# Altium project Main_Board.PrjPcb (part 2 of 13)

## Sheet LED_US_1.SchDoc: LED_US_1
size A3
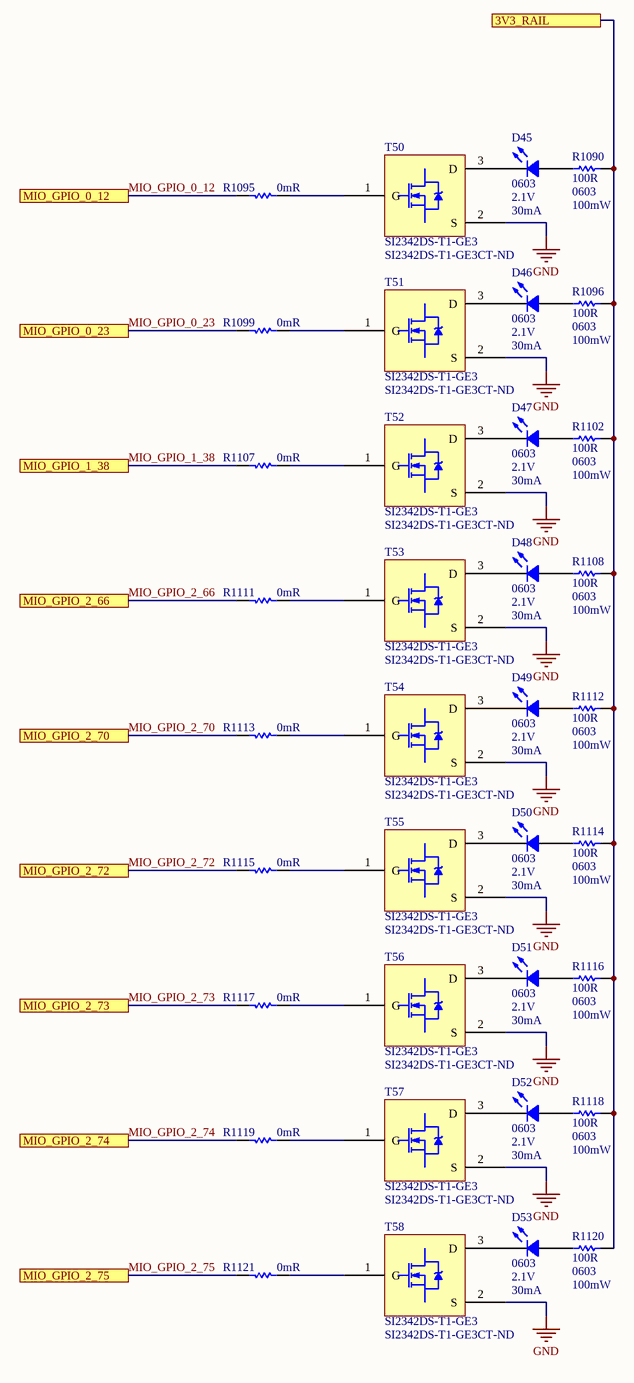
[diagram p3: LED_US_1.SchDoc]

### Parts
D45  Case Code (Imperial): 0603  Forward Voltage: 2.1V  Forward Current: 30mA  [LED 0603/1608 GREEN]  (hidden comment: LTST-C190GKT)
D46  Case Code (Imperial): 0603  Forward Voltage: 2.1V  Forward Current: 30mA  [LED 0603/1608 GREEN]  (hidden comment: LTST-C190GKT)
D47  Case Code (Imperial): 0603  Forward Voltage: 2.1V  Forward Current: 30mA  [LED 0603/1608 GREEN]  (hidden comment: LTST-C190GKT)
D48  Case Code (Imperial): 0603  Forward Voltage: 2.1V  Forward Current: 30mA  [LED 0603/1608 GREEN]  (hidden comment: LTST-C190GKT)
D49  Case Code (Imperial): 0603  Forward Voltage: 2.1V  Forward Current: 30mA  [LED 0603/1608 GREEN]  (hidden comment: LTST-C190GKT)
D50  Case Code (Imperial): 0603  Forward Voltage: 2.1V  Forward Current: 30mA  [LED 0603/1608 GREEN]  (hidden comment: LTST-C190GKT)
D51  Case Code (Imperial): 0603  Forward Voltage: 2.1V  Forward Current: 30mA  [LED 0603/1608 GREEN]  (hidden comment: LTST-C190GKT)
D52  Case Code (Imperial): 0603  Forward Voltage: 2.1V  Forward Current: 30mA  [LED 0603/1608 GREEN]  (hidden comment: LTST-C190GKT)
D53  Case Code (Imperial): 0603  Forward Voltage: 2.1V  Forward Current: 30mA  [LED 0603/1608 GREEN]  (hidden comment: LTST-C190GKT)
R1090  100R  Case/Package: 0603  Power Rating: 100mW  [RES 0603/1608 RF]
R1095  0mR  [RES 0402/1005 RF KK]
R1096  100R  Case/Package: 0603  Power Rating: 100mW  [RES 0603/1608 RF]
R1099  0mR  [RES 0402/1005 RF KK]
R1102  100R  Case/Package: 0603  Power Rating: 100mW  [RES 0603/1608 RF]
R1107  0mR  [RES 0402/1005 RF KK]
R1108  100R  Case/Package: 0603  Power Rating: 100mW  [RES 0603/1608 RF]
R1111  0mR  [RES 0402/1005 RF KK]
R1112  100R  Case/Package: 0603  Power Rating: 100mW  [RES 0603/1608 RF]
R1113  0mR  [RES 0402/1005 RF KK]
R1114  100R  Case/Package: 0603  Power Rating: 100mW  [RES 0603/1608 RF]
R1115  0mR  [RES 0402/1005 RF KK]
R1116  100R  Case/Package: 0603  Power Rating: 100mW  [RES 0603/1608 RF]
R1117  0mR  [RES 0402/1005 RF KK]
R1118  100R  Case/Package: 0603  Power Rating: 100mW  [RES 0603/1608 RF]
R1119  0mR  [RES 0402/1005 RF KK]
R1120  100R  Case/Package: 0603  Power Rating: 100mW  [RES 0603/1608 RF]
R1121  0mR  [RES 0402/1005 RF KK]
T50  SI2342DS-T1-GE3  Supplier Part Number 1: SI2342DS-T1-GE3CT-ND  [SI2342DS-T1-GE3]
T51  SI2342DS-T1-GE3  Supplier Part Number 1: SI2342DS-T1-GE3CT-ND  [SI2342DS-T1-GE3]
T52  SI2342DS-T1-GE3  Supplier Part Number 1: SI2342DS-T1-GE3CT-ND  [SI2342DS-T1-GE3]
T53  SI2342DS-T1-GE3  Supplier Part Number 1: SI2342DS-T1-GE3CT-ND  [SI2342DS-T1-GE3]
T54  SI2342DS-T1-GE3  Supplier Part Number 1: SI2342DS-T1-GE3CT-ND  [SI2342DS-T1-GE3]
T55  SI2342DS-T1-GE3  Supplier Part Number 1: SI2342DS-T1-GE3CT-ND  [SI2342DS-T1-GE3]
T56  SI2342DS-T1-GE3  Supplier Part Number 1: SI2342DS-T1-GE3CT-ND  [SI2342DS-T1-GE3]
T57  SI2342DS-T1-GE3  Supplier Part Number 1: SI2342DS-T1-GE3CT-ND  [SI2342DS-T1-GE3]
T58  SI2342DS-T1-GE3  Supplier Part Number 1: SI2342DS-T1-GE3CT-ND  [SI2342DS-T1-GE3]

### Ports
3V3_RAIL, MIO_GPIO_0_12, MIO_GPIO_0_23, MIO_GPIO_1_38, MIO_GPIO_2_66, MIO_GPIO_2_70, MIO_GPIO_2_72, MIO_GPIO_2_73, MIO_GPIO_2_74, MIO_GPIO_2_75

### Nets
GND: T50.2(S) T51.2(S) T52.2(S) T53.2(S) T54.2(S) T55.2(S) T56.2(S) T57.2(S) T58.2(S)  [project net B503_Ground]
3V3_RAIL: R1090.2 R1096.2 R1102.2 R1108.2 R1112.2 R1114.2 R1116.2 R1118.2 R1120.2 ; port 3V3_RAIL
MIO_GPIO_0_12: R1095.2 ; port MIO_GPIO_0_12
MIO_GPIO_0_23: R1099.2 ; port MIO_GPIO_0_23
MIO_GPIO_1_38: R1107.2 ; port MIO_GPIO_1_38
MIO_GPIO_2_66: R1111.2 ; port MIO_GPIO_2_66
MIO_GPIO_2_70: R1113.2 ; port MIO_GPIO_2_70
MIO_GPIO_2_72: R1115.2 ; port MIO_GPIO_2_72  [project net EXPANDER_RESET]
MIO_GPIO_2_73: R1117.2 ; port MIO_GPIO_2_73
MIO_GPIO_2_74: R1119.2 ; port MIO_GPIO_2_74
MIO_GPIO_2_75: R1121.2 ; port MIO_GPIO_2_75
NetD45_1: D45.1 R1090.1
NetD45_2: D45.2 T50.3(D)
NetD46_1: D46.1 R1096.1
NetD46_2: D46.2 T51.3(D)
NetD47_1: D47.1 R1102.1
NetD47_2: D47.2 T52.3(D)
NetD48_1: D48.1 R1108.1
NetD48_2: D48.2 T53.3(D)
NetD49_1: D49.1 R1112.1
NetD49_2: D49.2 T54.3(D)
NetD50_1: D50.1 R1114.1
NetD50_2: D50.2 T55.3(D)
NetD51_1: D51.1 R1116.1
NetD51_2: D51.2 T56.3(D)
NetD52_1: D52.1 R1118.1
NetD52_2: D52.2 T57.3(D)
NetD53_1: D53.1 R1120.1
NetD53_2: D53.2 T58.3(D)
NetR1095_1: R1095.1 T50.1(G)
NetR1099_1: R1099.1 T51.1(G)
NetR1107_1: R1107.1 T52.1(G)
NetR1111_1: R1111.1 T53.1(G)
NetR1113_1: R1113.1 T54.1(G)
NetR1115_1: R1115.1 T55.1(G)
NetR1117_1: R1117.1 T56.1(G)
NetR1119_1: R1119.1 T57.1(G)
NetR1121_1: R1121.1 T58.1(G)

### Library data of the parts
D45-D53 = LTST-C190GKT: LED,  LTST-C190GKT; Manufacturer 1: Vishay Lite-On; Color: Green; Lens Color: Colorless; Luminous Intensity: 6mcd; Viewing Angle: 130°; Lens Style: Clear,Diffused,Colorless,Rectangular; Power Rating: 100mW; Dominant Wavelength: 569nm; Test Current: 10mA; Lens Transparency: Clear; Number of Elements: 1; Wavelength: 565nm; Voltage: 2V; Reverse Voltage: 5V
R1090 R1096 R1102 R1108 R1112 R1114 R1116 R1118 R1120 = Resistor: KOA SPEAR ELECTRONICS - RK73H1JTTD1000F - RES, 100R, 1%, 0.1W, 0603, THICK FILM; Manufacturer: KOA Speer; Voltage Rating: 50V; Temperature Coefficient: 100ppm/°C
R1095 R1099 R1107 R1111 R1113 R1115 R1117 R1119 R1121 = Resistor: Manufacturer 1: Yageo; Manufacturer Part Number 1: RC0402JR-070RL; Power Rating: 62.5mW; Tolerance: 5%; Voltage Rating: 50V; Max Power Dissipation: 63mW; Temperature Coefficient: 200ppm/°C
T50-T58 = SI2342DS-T1-GE3: Trans MOSFET N-CH 8V 6A 3-Pin SOT-23 T/R; Manufacturer: Vishay; Rds On Max: 17mR; Input Capacitance: 1.07nF; Rise Time: 14ns; Max Power Dissipation: 2.5W; Number of Elements: 1; Power Dissipation: 1.3W; Turn-On Delay Time: 6ns; Turn-Off Delay Time: 65ns; Fall Time: 25ns; Threshold Voltage: 800mV; Gate to Source Voltage (Vgs): 5V

## Sheet WR_Clock.SchDoc: WR_Generator
size A3; Organization: Altium Limited; Address1: L3, 12a Rodborough Rd; Address2: Frenchs Forest; Address3: NSW; Address4: Australia 2086
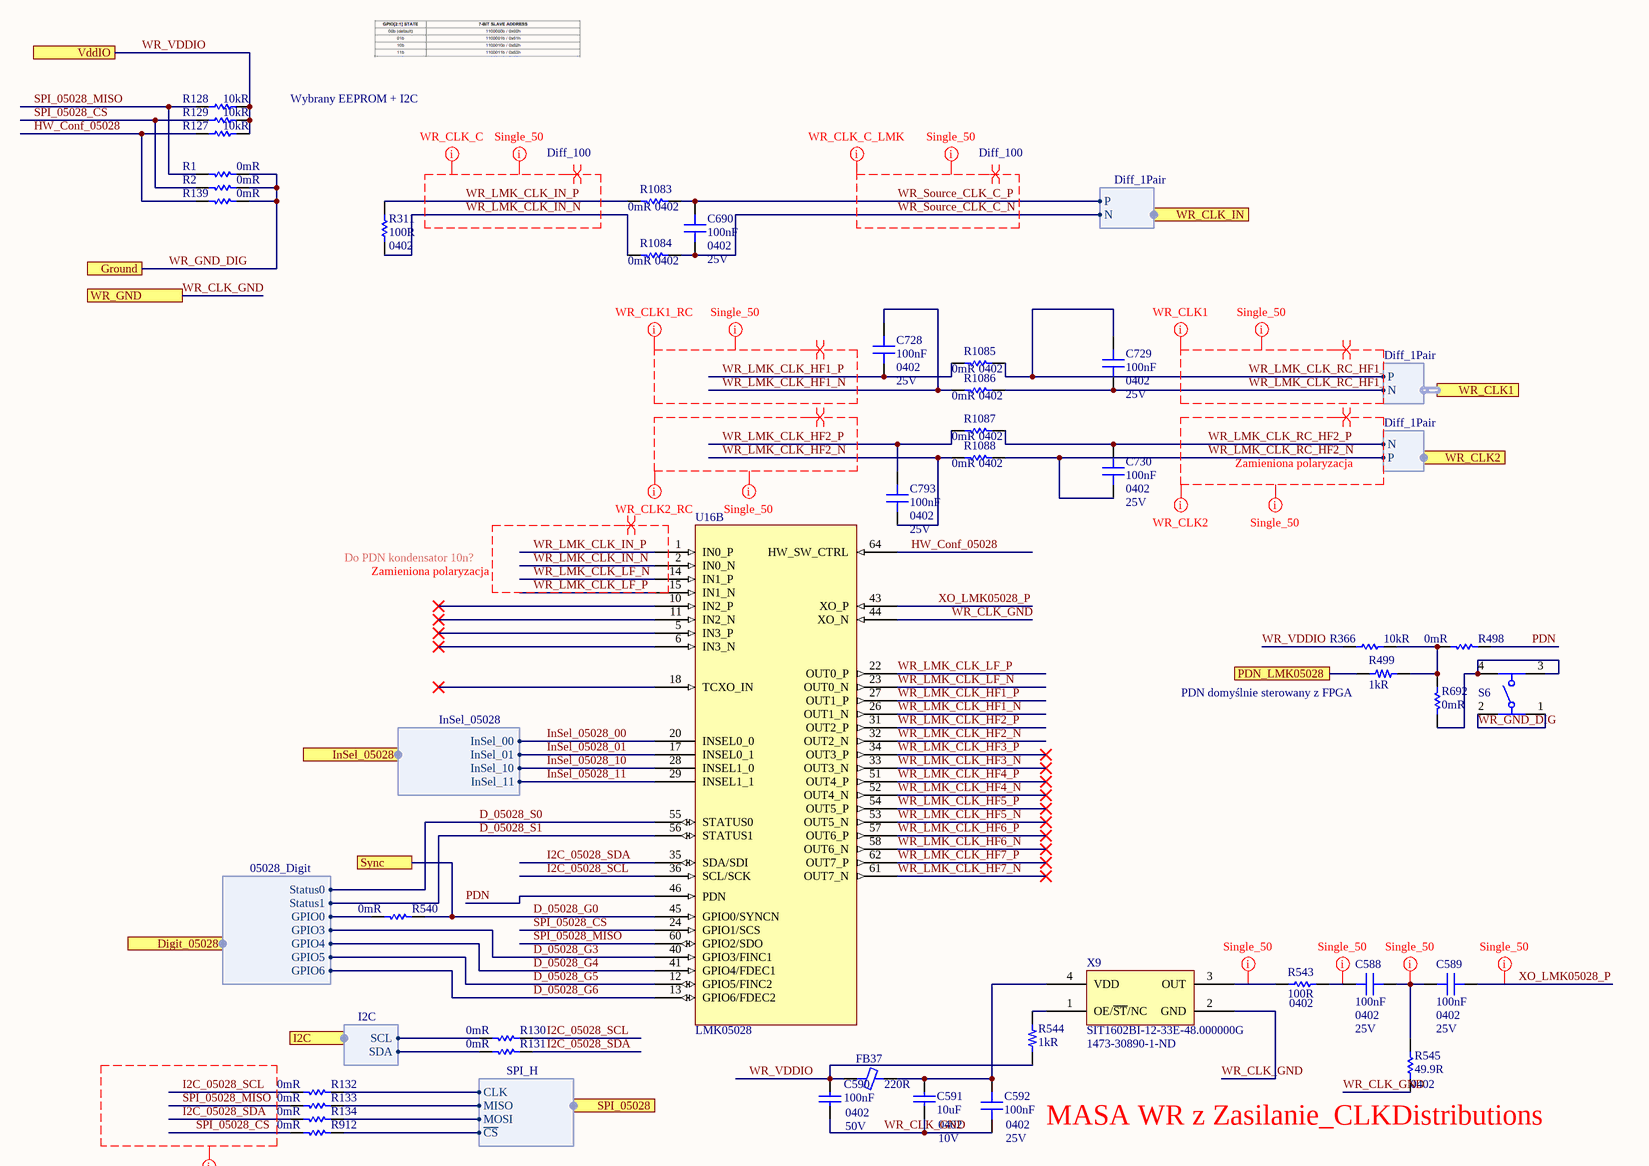
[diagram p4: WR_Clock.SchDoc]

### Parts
C588  100nF  Case/Package: 0402  Voltage Rating: 25V  [CAP 0402/1005 KK]
C589  100nF  Case/Package: 0402  Voltage Rating: 25V  [CAP 0402/1005 KK]
C590  100nF  Case Code (Imperial): 0402  Voltage: 50V  [CAP 0402/1005 KK]
C591  10uF  Case/Package: 0402  Voltage Rating: 10V  [CAP 0402/1005 KK]
C592  100nF  Case/Package: 0402  Voltage Rating: 25V  [CAP 0402/1005 KK]
C690  100nF  Case/Package: 0402  Voltage Rating: 25V  [CAP 0402/1005 KK]
C728  100nF  Case/Package: 0402  Voltage Rating: 25V  [CAP 0402/1005 KK]
C729  100nF  Case/Package: 0402  Voltage Rating: 25V  [CAP 0402/1005 KK]
C730  100nF  Case/Package: 0402  Voltage Rating: 25V  [CAP 0402/1005 KK]
C793  100nF  Case/Package: 0402  Voltage Rating: 25V  [CAP 0402/1005 KK]
FB37  220R  [FER 0603/1608]
R1  0mR  [RES 0402/1005 RF KK]
R2  0mR  [RES 0402/1005 RF KK]
R127  10kR  [RES 0402/1005 RF KK]
R128  10kR  [RES 0402/1005 RF KK]
R129  10kR  [RES 0402/1005 RF KK]
R130  0mR  [RES 0402/1005 RF KK]
R131  0mR  [RES 0402/1005 RF KK]
R132  0mR  [RES 0402/1005 RF KK]
R133  0mR  [RES 0402/1005 RF KK]
R134  0mR  [RES 0402/1005 RF KK]
R139  0mR  [RES 0402/1005 RF KK]
R311  100R  Case/Package: 0402  [RES 0402/1005 RF KK]
R366  10kR  [RES 0402/1005 RF KK]
R498  0mR  [RES 0402/1005 RF KK]
R499  1kR  [RES 0402/1005 RF KK]
R540  0mR  [RES 0402/1005 RF KK]
R543  100R  Case/Package: 0402  [RES 0402/1005 RF KK]
R544  1kR  [RES 0402/1005 RF KK]
R545  49.9R  Case/Package: 0402  [RES 0402/1005 RF KK]
R692  0mR  [RES 0402/1005 RF KK]
R912  0mR  [RES 0402/1005 RF KK]
R1083  0mR  Case/Package: 0402  [RES 0402/1005 RF KK]
R1084  0mR  Case/Package: 0402  [RES 0402/1005 RF KK]
R1085  0mR  Case/Package: 0402  [RES 0402/1005 RF KK]
R1086  0mR  Case/Package: 0402  [RES 0402/1005 RF KK]
R1087  0mR  Case/Package: 0402  [RES 0402/1005 RF KK]
R1088  0mR  Case/Package: 0402  [RES 0402/1005 RF KK]
S6  430181038816  [430181038816]  (value not drawn)
U16  LMK05028  [LMK05028]  (part B of 2)
X9  SIT1602BI-12-33E-48.000000G  Supplier Part Number 1: 1473-30890-1-ND  [SiT1602B]

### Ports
Digit_05028 (harness 05028_Digit), Ground, I2C (harness I2C), InSel_05028 (harness InSel_05028), PDN_LMK05028, SPI_05028 (harness SPI_H), Sync, VddIO, WR_CLK1 (harness Diff_1Pair), WR_CLK2 (harness Diff_1Pair), WR_CLK_IN (harness Diff_1Pair), WR_GND

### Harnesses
SPI_H: CLK, MISO, MOSI, ~{CS}
I2C: SDA, SCL
05028_Digit: GPIO4, GPIO3, Status0, GPIO6, Status1, GPIO5, GPIO0
Diff_1Pair: N, P
InSel_05028: InSel_00, InSel_01, InSel_10, InSel_11

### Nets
WR_GND_DIG: R1.1 R2.1 R139.1 S6.1 S6.2 ; port Ground  [project net B503_Ground]
D_05028_G0: R540.1 U16.45(GPIO0/SYNCN) ; port Sync
D_05028_G3: U16.40(GPIO3/FINC1) ; port Digit_05028.GPIO3
D_05028_G4: U16.41(GPIO4/FDEC1) ; port Digit_05028.GPIO4
D_05028_G5: U16.12(GPIO5/FINC2) ; port Digit_05028.GPIO5
D_05028_G6: U16.13(GPIO6/FDEC2) ; port Digit_05028.GPIO6
D_05028_S0: U16.55(STATUS0) ; port Digit_05028.Status0
D_05028_S1: U16.56(STATUS1) ; port Digit_05028.Status1
GPIOa_11.GPIO7: R499.1 ; port PDN_LMK05028
GPIOb_12.GPIO2: R540.2 ; port Digit_05028.GPIO0
HW_Conf_05028: R127.1 R139.2 U16.64(HW_SW_CTRL)
I2C_05028_SCL: R130.1 R132.2 U16.36(SCL/SCK)
I2C_05028_SDA: R131.1 R134.2 U16.35(SDA/SDI)
InSel_05028_00: U16.20(INSEL0_0) ; port InSel_05028.InSel_00  [project net GPIOb_00.GPIO6]
InSel_05028_01: U16.17(INSEL0_1) ; port InSel_05028.InSel_01  [project net GPIOb_00.GPIO7]
InSel_05028_10: U16.28(INSEL1_0) ; port InSel_05028.InSel_10  [project net GPIOb_00.GPIO5]
InSel_05028_11: U16.29(INSEL1_1) ; port InSel_05028.InSel_11  [project net GPIOb_00.GPIO4]
PDN: R498.1 U16.46(PDN)
SFP_I2C4.SCL: R130.2 ; port I2C.SCL
SFP_I2C4.SDA: R131.2 ; port I2C.SDA
SPI_05028_CS: R2.2 R129.1 R912.2 U16.24(GPIO1/SCS)
SPI_05028_MISO: R1.2 R128.1 R133.2 U16.60(GPIO2/SDO)
WR_CLK_GND: C590.1 C591.1 C592.1 R545.1 U16.44(XO_N) X9.2(GND) ; port WR_GND  [project net Ground]
WR_LMK_CLK_HF1_N: C728.1 R1086.2 U16.26(OUT1_N)
WR_LMK_CLK_HF1_P: C728.2 R1085.2 U16.27(OUT1_P)
WR_LMK_CLK_HF2_N: C793.2 R1088.2 U16.32(OUT2_N)
WR_LMK_CLK_HF2_P: C793.1 R1087.2 U16.31(OUT2_P)
WR_LMK_CLK_HF3_N: U16.33(OUT3_N)
WR_LMK_CLK_HF3_P: U16.34(OUT3_P)
WR_LMK_CLK_HF4_N: U16.52(OUT4_N)
WR_LMK_CLK_HF4_P: U16.51(OUT4_P)
WR_LMK_CLK_HF5_N: U16.53(OUT5_N)
WR_LMK_CLK_HF5_P: U16.54(OUT5_P)
WR_LMK_CLK_HF6_N: U16.58(OUT6_N)
WR_LMK_CLK_HF6_P: U16.57(OUT6_P)
WR_LMK_CLK_HF7_N: U16.61(OUT7_N)
WR_LMK_CLK_HF7_P: U16.62(OUT7_P)
WR_LMK_CLK_IN_N: R311.1 R1084.2 U16.2(IN0_N)
WR_LMK_CLK_IN_P: R311.2 R1083.2 U16.1(IN0_P)
WR_LMK_CLK_LF_N: U16.14(IN1_P) U16.23(OUT0_N)
WR_LMK_CLK_LF_P: U16.15(IN1_N) U16.22(OUT0_P)
WR_LMK_CLK_RC_HF1_N: C729.2 R1086.1 ; port WR_CLK1.N
WR_LMK_CLK_RC_HF1_P: C729.1 R1085.1 ; port WR_CLK1.P
WR_LMK_CLK_RC_HF2_N: C730.2 R1088.1 ; port WR_CLK2.P
WR_LMK_CLK_RC_HF2_P: C730.1 R1087.1 ; port WR_CLK2.N
WR_Source_CLK_C_N: C690.2 R1084.1 ; port WR_CLK_IN.N  [project net LTC6952_1_MATCH_Out8_N]
WR_Source_CLK_C_P: C690.1 R1083.1 ; port WR_CLK_IN.P  [project net LTC6952_1_MATCH_Out8_P]
WR_VDDIO: C590.2 FB37.1 R127.2 R128.2 R129.2 R366.1 R544.2 ; port VddIO  [project net VDD_DIG]
XO_LMK05028_P: C589.1 U16.43(XO_P)
NetC588_1: C588.1 C589.2 R545.2
NetC588_2: C588.2 R543.2
NetC591_2: C591.2 C592.2 FB37.2 X9.4(VDD)
NetR132_1: R132.1 ; port SPI_05028.CLK
NetR133_1: R133.1 ; port SPI_05028.MISO
NetR134_1: R134.1 ; port SPI_05028.MOSI
NetR240_SPI_bridge_Main_1: R912.1 ; port SPI_05028.~{CS}
NetR366_2: R366.2 R498.2 R499.2 R692.1
NetR543_1: R543.1 X9.3(OUT)
NetR544_1: R544.1 X9.1(OE/~{ST}/NC)
NetR692_2: R692.2 S6.3 S6.4

Not connected (* = marked no-connect by the designer): U16 5(IN3_P)* 6(IN3_N)* 10(IN2_P)* 11(IN2_N)* 18(TCXO_IN)*

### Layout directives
net class Single_50: NetC588_1, NetC588_2, NetR543_1, WR_LMK_CLK_HF1_N, WR_LMK_CLK_HF1_P, WR_LMK_CLK_HF2_N, WR_LMK_CLK_HF2_P, WR_LMK_CLK_IN_N, WR_LMK_CLK_IN_P, WR_LMK_CLK_RC_HF1_N, WR_LMK_CLK_RC_HF1_P, WR_LMK_CLK_RC_HF2_N, WR_LMK_CLK_RC_HF2_P, WR_Source_CLK_C_N, WR_Source_CLK_C_P, XO_LMK05028_P
net class WR_CLK1: WR_LMK_CLK_RC_HF1_N, WR_LMK_CLK_RC_HF1_P
net class WR_CLK2: WR_LMK_CLK_RC_HF2_N, WR_LMK_CLK_RC_HF2_P
net class WR_CLK_C_LMK: WR_Source_CLK_C_N, WR_Source_CLK_C_P
differential pair; differential pair class Diff_100: WR_LMK_CLK_HF1_N, WR_LMK_CLK_HF1_P, WR_LMK_CLK_HF2_N, WR_LMK_CLK_HF2_P, WR_LMK_CLK_IN_N, WR_LMK_CLK_IN_P, WR_LMK_CLK_LF_N, WR_LMK_CLK_LF_P, WR_LMK_CLK_RC_HF1_N, WR_LMK_CLK_RC_HF1_P, WR_LMK_CLK_RC_HF2_N, WR_LMK_CLK_RC_HF2_P, WR_Source_CLK_C_N, WR_Source_CLK_C_P
net class WR_CLK_C: WR_LMK_CLK_IN_N, WR_LMK_CLK_IN_P
net class WR_CLK2_RC: WR_LMK_CLK_HF2_N, WR_LMK_CLK_HF2_P
net class WR_CLK1_RC: WR_LMK_CLK_HF1_N, WR_LMK_CLK_HF1_P
net class SPI_05028: I2C_05028_SCL, I2C_05028_SDA, SPI_05028_CS, SPI_05028_MISO

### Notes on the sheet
- Wybrany EEPROM + I2C
- Zamieniona polaryzacja
- Do PDN kondensator 10n?
- (near R499) PDN domyślnie sterowany z FPGA
- (near R545) MASA WR z Zasilanie_CLKDistributions

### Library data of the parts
C588 C589 C592 C690 C728-C730 C793 = Capacitor: Manufacturer: Murata; Manufacturer Part Number: GRM155R71E104KE14J; Tolerance: 10%; Dielectric: X7R
C590 = Capacitor: CAP CER 0.1UF 50V X5R 0402; Manufacturer: Murata; Manufacturer Part Number: GRM155R61H104KE14D; Dielectric Material: Ceramic; Dissipation Factor: 0.025%; Tolerance: 10%
C591 = Capacitor: CAP CER 10UF 10V X5R 0402; Manufacturer: Samsung; Manufacturer Part Number: CL05A106MP8NUB8; Tolerance: 20%
FB37 = Ferrite: FERRITE BEAD 220 OHM 0603 1LN; Manufacturer: Murata; Manufacturer Part Number: BLM18SG221TN1D; Material: Ferrite,Steel; Tolerance: 25%; Max Current Rating: 2.5A; Number of Lines: 1; DC Resistance (DCR): 40mR; Test Frequency: 100MHz
R1 R2 R130-R134 R139 R498 R540 R692 R912 R1083-R1088 = Resistor: as R1095 on sheet LED_US_1
R127-R129 R366 = Resistor: Manufacturer 1: Yageo; Manufacturer Part Number 1: RC0402FR-0710KL; Tolerance: 1%; Temperature Coefficient: 100ppm/°C; Voltage Rating: 50V; Power Rating: 62.5mW
R311 R543 = Resistor: RES SMD 100 OHM 1% 1/16W 0402; Manufacturer: Yageo; Manufacturer Part Number: RC0402FR-07100RL; Power Rating: 62.5mW; Voltage Rating: 50V; Temperature Coefficient: 100ppm/°C
R499 R544 = Resistor: Manufacturer: Panasonic; Manufacturer Part Number: ERJ-2RKF1001X; Tolerance: 1%; Power Rating: 100mW; Temperature Coefficient: 100ppm/°C; Voltage Rating: 50V
R545 = Resistor: RES SMD 49.9 OHM 1% 1/16W 0402; Manufacturer: Yageo; Manufacturer Part Number: RC0402FR-0749R9L; Voltage Rating (DC): 50V; Power Rating: 62.5mW; Temperature Coefficient: 100ppm/°C; Max Power Dissipation: 63mW
S6 = 430181038816: WS-TASV SMT Tact Switch 4.5x4.5mm, height 3.8mm, 160gf; Rated Voltage: 12VDC; Rated Current: 50mA; Washable: No
U16 = LMK05028: Manufacturer Part Number: LMK05028RGCR; Manufacturer: Texas Instruments; Number of Inputs: 4; Number of Outputs: 8
X9 = SIT1602BI-12-33E-48.000000G: OSC MEMS 48.0000MHZ LVCMOS SMD; Manufacturer: SiTime; Frequency: 48MHz; Max Supply Current: 4.5mA; Frequency Stability: 25ppm

## Sheet System_CLK.SchDoc: Dystrybutory zegarów
size A3; Organization: Altium Limited; Address1: L3, 12a Rodborough Rd; Address2: Frenchs Forest; Address3: NSW; Address4: Australia 2086
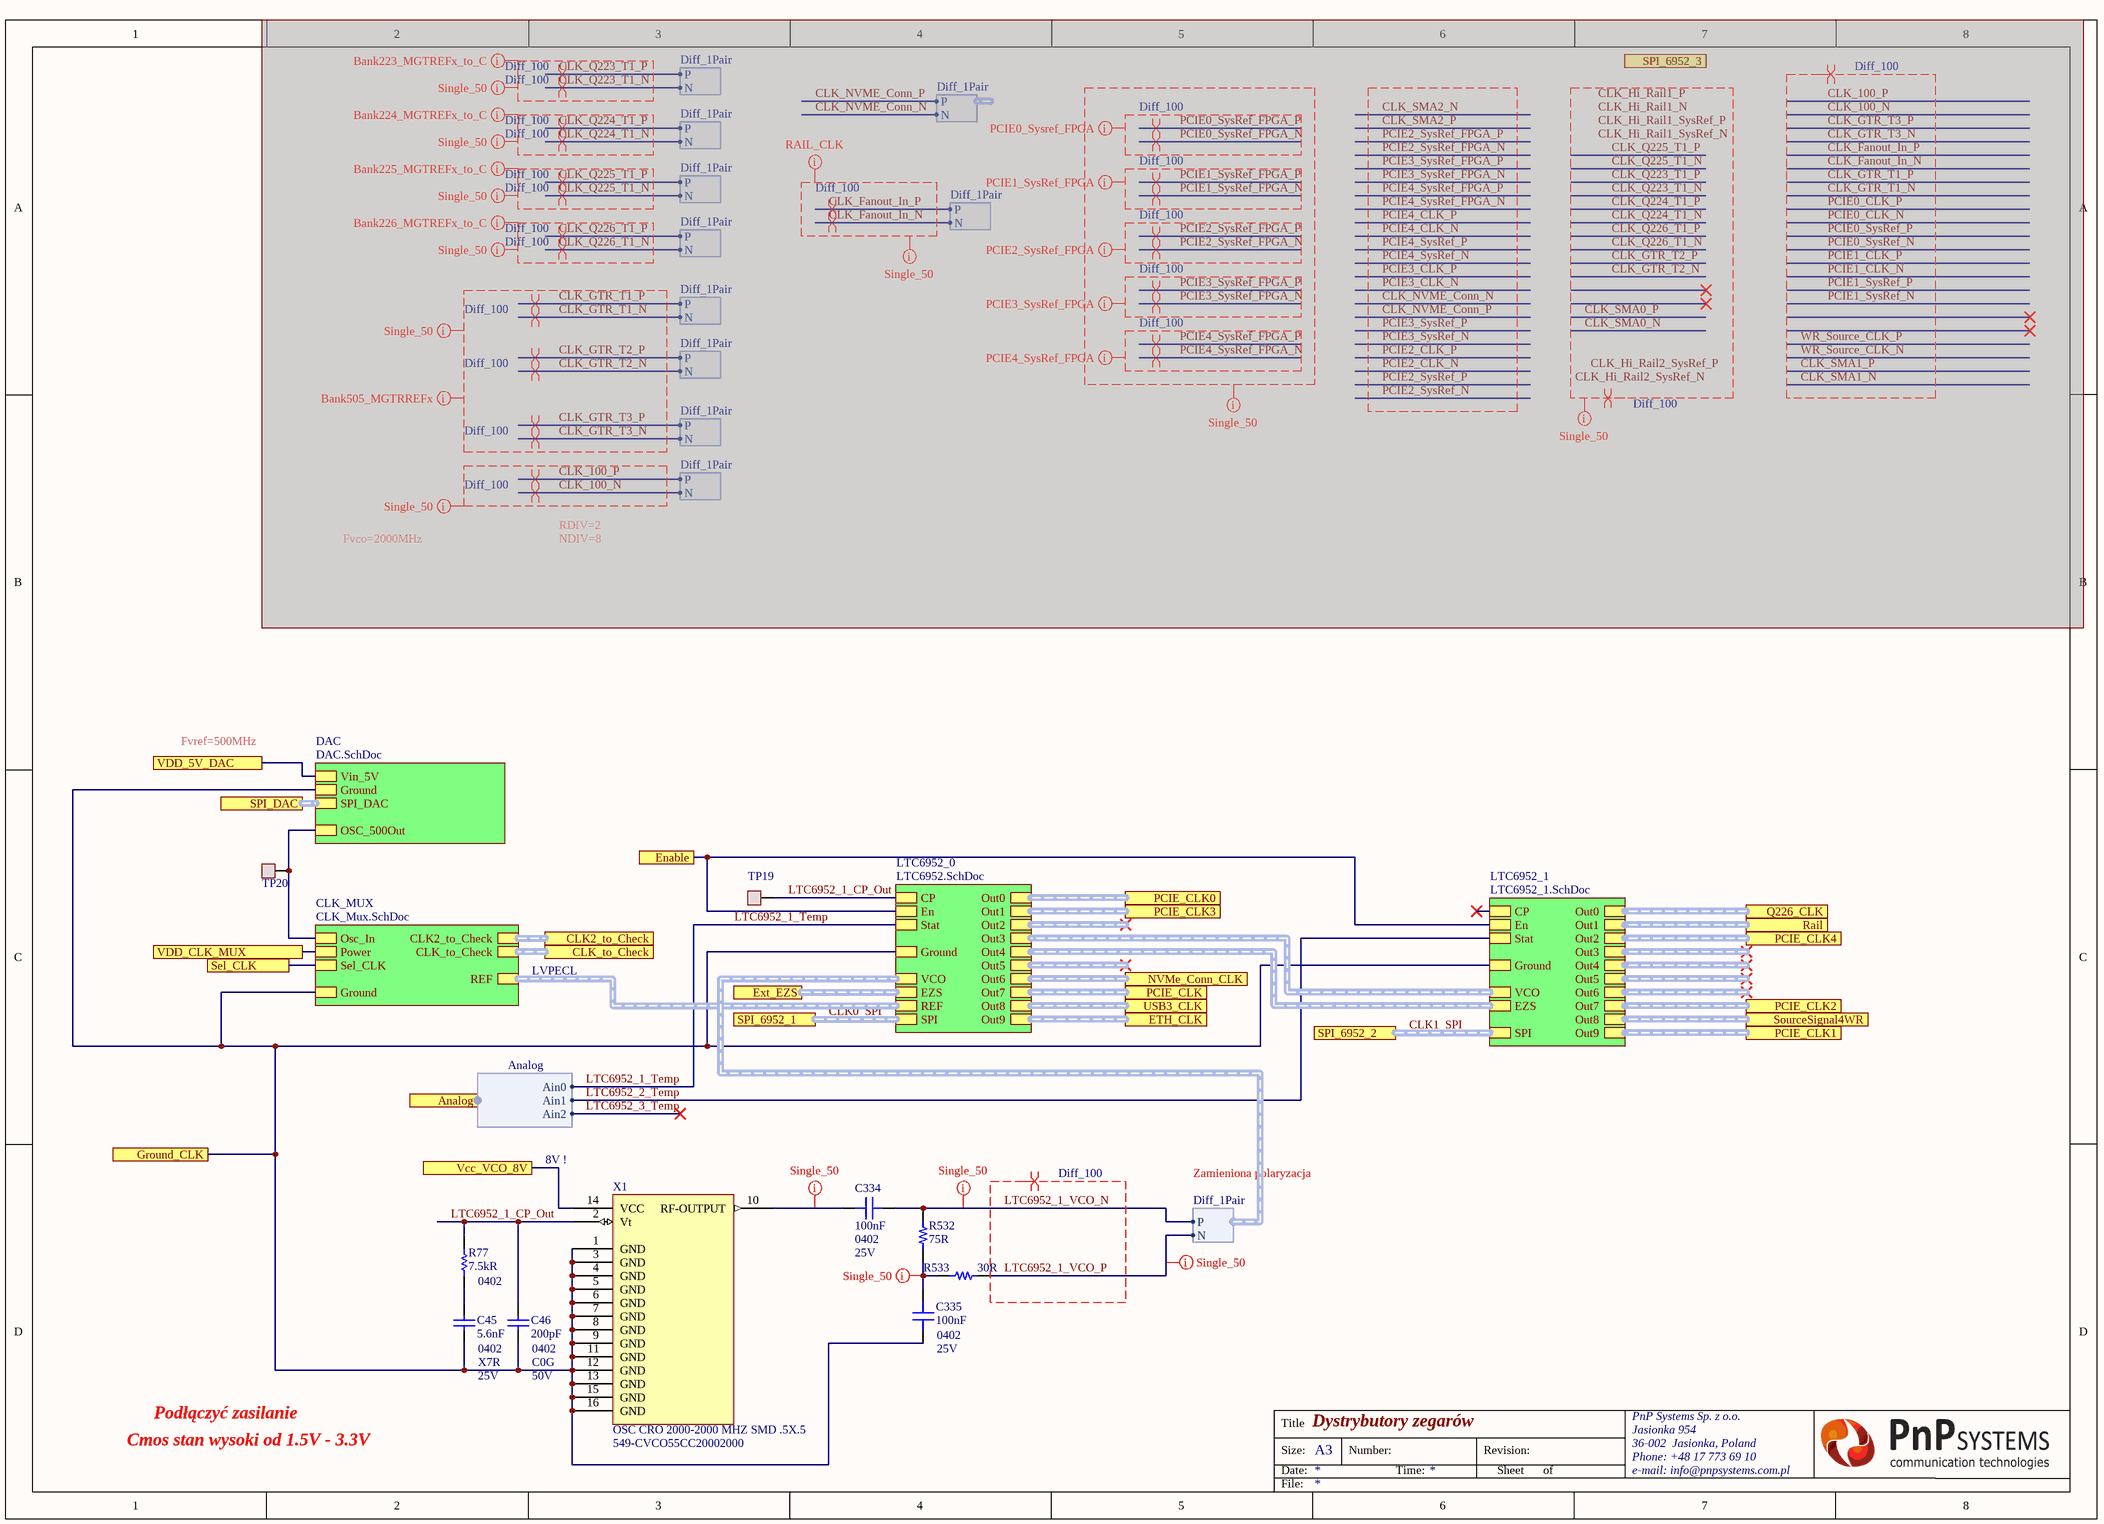
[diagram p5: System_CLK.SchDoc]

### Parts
C45  5.6nF  Case Code (Imperial): 0402  Voltage Rating: 25V  Dielectric: X7R  [CAP 0402/1005 KK]
C46  200pF  Case/Package: 0402  Voltage Rating: 50V  Dielectric: C0G  [CAP 0402/1005 KK]
C334  100nF  Case/Package: 0402  Voltage Rating: 25V  [CAP 0402/1005 KK]
C335  100nF  Case/Package: 0402  Voltage Rating: 25V  [CAP 0402/1005 KK]
R77  7.5kR  Case Code (Imperial): 0402  [RES 0402/1005 RF KK]
R532  75R  [RES 0402/1005 RF KK]
R533  30R  [RES 0402/1005 RF KK]
TP19  TestPoint  [TestPoint]  (value not drawn)
TP20  TestPoint  [TestPoint]  (value not drawn)
X1  OSC CRO 2000-2000 MHZ SMD .5X.5  Supplier Part Number 1: 549-CVCO55CC20002000  [CVCO55CW]

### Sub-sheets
CLK_MUX = CLK_Mux.SchDoc: Sel_CLK, REF (harness Diff_1Pair), Osc_In, Ground, Power, CLK_to_Check (harness Diff_1Pair), CLK2_to_Check (harness Diff_1Pair)
DAC = DAC.SchDoc: Vin_5V, SPI_DAC (harness SPI_H), Ground, OSC_500Out
LTC6952_0 = LTC6952.SchDoc: CP, Ground, Out6 (harness Diff_1Pair), VCO (harness Diff_1Pair), SPI (harness SPI_H), Stat, Out1 (harness Diff_1Pair), En, Out5 (harness Diff_1Pair), Out0 (harness Diff_1Pair), EZS (harness Diff_1Pair), Out2 (harness Diff_1Pair), Out7 (harness Diff_1Pair), REF (harness Diff_1Pair), Out8 (harness Diff_1Pair), Out3 (harness Diff_1Pair), Out4 (harness Diff_1Pair), Out9 (harness Diff_1Pair)
LTC6952_1 = LTC6952_1.SchDoc: EZS (harness Diff_1Pair), SPI (harness SPI_H), En, Out5 (harness Diff_1Pair), Ground, CP, Out4 (harness Diff_1Pair), Out6 (harness Diff_1Pair), VCO (harness Diff_1Pair), Out9 (harness Diff_1Pair), Stat, Out7 (harness Diff_1Pair), Out3 (harness Diff_1Pair), Out0 (harness Diff_1Pair), Out8 (harness Diff_1Pair), Out2 (harness Diff_1Pair), Out1 (harness Diff_1Pair)

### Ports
Analog (harness Analog), CLK2_to_Check (harness Diff_1Pair), CLK_to_Check (harness Diff_1Pair), Enable, ETH_CLK (harness Diff_1Pair), Ext_EZS (harness Diff_1Pair), Ground_CLK, NVMe_Conn_CLK (harness Diff_1Pair), PCIE_CLK0 (harness Diff_1Pair), PCIE_CLK1 (harness Diff_1Pair), PCIE_CLK2 (harness Diff_1Pair), PCIE_CLK3 (harness Diff_1Pair), PCIE_CLK4 (harness Diff_1Pair), PCIE_CLK (harness Diff_1Pair), Q226_CLK (harness Diff_1Pair), Rail (harness Diff_1Pair), Sel_CLK, SourceSignal4WR (harness Diff_1Pair), SPI_6952_1 (harness SPI_H), SPI_6952_2 (harness SPI_H), SPI_6952_3 (harness SPI_H), SPI_DAC (harness SPI_H), USB3_CLK (harness Diff_1Pair), Vcc_VCO_8V, VDD_5V_DAC, VDD_CLK_MUX

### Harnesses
Diff_1Pair: P, N
Analog: Ain0, Ain1, Ain2

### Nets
3V3_RAIL: port VDD_CLK_MUX, sheet CLK_MUX/Power
5V_LN: port VDD_5V_DAC, sheet DAC/Vin_5V
AGND: C45.1 C46.1 C335.1 X1.1(GND) X1.3(GND) X1.4(GND) X1.5(GND) X1.6(GND) X1.7(GND) X1.8(GND) X1.9(GND) X1.11(GND) X1.12(GND) X1.13(GND) X1.15(GND) X1.16(GND) ; port Ground_CLK, sheet DAC/Ground, sheet CLK_MUX/Ground, sheet LTC6952_1/Ground, sheet LTC6952_0/Ground
Enable_CLK: port Enable, sheet LTC6952_1/En, sheet LTC6952_0/En
LTC6952_1_CP_Out: C46.2 R77.2 TP19.1 X1.2(Vt) ; sheet LTC6952_0/CP
LTC6952_1_Temp: sheet LTC6952_0/Stat, port Analog.Ain0
LTC6952_1_VCO_N: C334.1 R532.2 ; sheet LTC6952_0/VCO.P
LTC6952_1_VCO_P: R533.2 ; sheet LTC6952_0/VCO.N
LTC6952_2_Temp: sheet LTC6952_1/Stat, port Analog.Ain1
OSC_500Out: TP20.1 ; sheet DAC/OSC_500Out, sheet CLK_MUX/Osc_In
SetClk_Si53323_2: port Sel_CLK, sheet CLK_MUX/Sel_CLK
NetC45_2: C45.2 R77.1
NetC334_2: C334.2 X1.10(RF-OUTPUT)
NetC335_2: C335.2 R532.1 R533.1
NetC713_2: X1.14(VCC) ; port Vcc_VCO_8V

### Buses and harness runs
harness CLK0_SPI = port SPI_6952_1 = sheet LTC6952_0/SPI
harness CLK1_SPI = port SPI_6952_2 = sheet LTC6952_1/SPI
harness port CLK2_to_Check = sheet CLK_MUX/CLK2_to_Check
harness port CLK_to_Check = sheet CLK_MUX/CLK_to_Check
harness port ETH_CLK = sheet LTC6952_0/Out9
harness port Ext_EZS = sheet LTC6952_0/EZS
harness port NVMe_Conn_CLK = sheet LTC6952_0/Out6
harness port PCIE_CLK0 = sheet LTC6952_0/Out0
harness port PCIE_CLK1 = sheet LTC6952_1/Out9
harness port PCIE_CLK2 = sheet LTC6952_1/Out7
harness port PCIE_CLK3 = sheet LTC6952_0/Out1
harness port PCIE_CLK4 = sheet LTC6952_1/Out2
harness port PCIE_CLK = sheet LTC6952_0/Out7
harness port Q226_CLK = sheet LTC6952_1/Out0
harness port Rail = sheet LTC6952_1/Out1
harness port SourceSignal4WR = sheet LTC6952_1/Out8
harness port SPI_DAC = sheet DAC/SPI_DAC
harness port USB3_CLK = sheet LTC6952_0/Out8
harness sheet CLK_MUX/REF = sheet LTC6952_0/REF
harness sheet LTC6952_0/Out3 = sheet LTC6952_1/VCO
harness sheet LTC6952_0/Out4 = sheet LTC6952_1/EZS

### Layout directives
net class Bank223_MGTREFx_to_C: CLK_Q223_T1_N, CLK_Q223_T1_P
net class Bank224_MGTREFx_to_C: CLK_Q224_T1_N, CLK_Q224_T1_P
net class Bank225_MGTREFx_to_C: CLK_Q225_T1_N, CLK_Q225_T1_P
net class Bank226_MGTREFx_to_C: CLK_Q226_T1_N, CLK_Q226_T1_P
differential pair; differential pair class Diff_100: CLK_100_N, CLK_100_P, CLK_Fanout_In_N, CLK_Fanout_In_P, CLK_GTR_T1_N, CLK_GTR_T1_P, CLK_GTR_T2_N, CLK_GTR_T2_P, CLK_GTR_T3_N, CLK_GTR_T3_P, CLK_Hi_Rail1_N, CLK_Hi_Rail1_P, CLK_Hi_Rail1_SysRef_N, CLK_Hi_Rail1_SysRef_P, CLK_Hi_Rail2_SysRef_N, CLK_Hi_Rail2_SysRef_P, CLK_Q223_T1_N, CLK_Q223_T1_P, CLK_Q224_T1_N, CLK_Q224_T1_P, CLK_Q225_T1_N, CLK_Q225_T1_P, CLK_Q226_T1_N, CLK_Q226_T1_P, CLK_SMA0_N, CLK_SMA0_P, CLK_SMA1_N, CLK_SMA1_P, LTC6952_1_VCO_N, LTC6952_1_VCO_P, PCIE0_CLK_N, PCIE0_CLK_P, PCIE0_SysRef_FPGA_N, PCIE0_SysRef_FPGA_P, PCIE0_SysRef_N, PCIE0_SysRef_P, PCIE1_CLK_N, PCIE1_CLK_P, PCIE1_SysRef_FPGA_N, PCIE1_SysRef_FPGA_P, PCIE1_SysRef_N, PCIE1_SysRef_P, PCIE2_SysRef_FPGA_N, PCIE2_SysRef_FPGA_P, PCIE3_SysRef_FPGA_N, PCIE3_SysRef_FPGA_P, PCIE4_SysRef_FPGA_N, PCIE4_SysRef_FPGA_P, WR_Source_CLK_N, WR_Source_CLK_P
net class Single_50: CLK_100_N, CLK_100_P, CLK_Fanout_In_N, CLK_Fanout_In_P, CLK_GTR_T1_N, CLK_GTR_T1_P, CLK_GTR_T2_N, CLK_GTR_T2_P, CLK_GTR_T3_N, CLK_GTR_T3_P, CLK_Hi_Rail1_N, CLK_Hi_Rail1_P, CLK_Hi_Rail1_SysRef_N, CLK_Hi_Rail1_SysRef_P, CLK_Hi_Rail2_SysRef_N, CLK_Hi_Rail2_SysRef_P, CLK_Q223_T1_N, CLK_Q223_T1_P, CLK_Q224_T1_N, CLK_Q224_T1_P, CLK_Q225_T1_N, CLK_Q225_T1_P, CLK_Q226_T1_N, CLK_Q226_T1_P, CLK_SMA0_N, CLK_SMA0_P, LTC6952_1_VCO_N, LTC6952_1_VCO_P, NetC334_2, NetC335_2, PCIE0_SysRef_FPGA_N, PCIE0_SysRef_FPGA_P, PCIE1_SysRef_FPGA_N, PCIE1_SysRef_FPGA_P, PCIE2_SysRef_FPGA_N, PCIE2_SysRef_FPGA_P, PCIE3_SysRef_FPGA_N, PCIE3_SysRef_FPGA_P, PCIE4_SysRef_FPGA_N, PCIE4_SysRef_FPGA_P
net class Bank505_MGTRREFx_: CLK_GTR_T1_N, CLK_GTR_T1_P, CLK_GTR_T2_N, CLK_GTR_T2_P, CLK_GTR_T3_N, CLK_GTR_T3_P
net class RAIL_CLK: CLK_Fanout_In_N, CLK_Fanout_In_P
net class PCIE0_Sysref_FPGA: PCIE0_SysRef_FPGA_N, PCIE0_SysRef_FPGA_P, PCIE1_SysRef_FPGA_N, PCIE1_SysRef_FPGA_P, PCIE2_SysRef_FPGA_N, PCIE2_SysRef_FPGA_P, PCIE3_SysRef_FPGA_N, PCIE3_SysRef_FPGA_P, PCIE4_SysRef_FPGA_N, PCIE4_SysRef_FPGA_P
net class PCIE1_SysRef_FPGA: PCIE0_SysRef_FPGA_N, PCIE0_SysRef_FPGA_P, PCIE1_SysRef_FPGA_N, PCIE1_SysRef_FPGA_P, PCIE2_SysRef_FPGA_N, PCIE2_SysRef_FPGA_P, PCIE3_SysRef_FPGA_N, PCIE3_SysRef_FPGA_P, PCIE4_SysRef_FPGA_N, PCIE4_SysRef_FPGA_P
net class PCIE2_SysRef_FPGA: PCIE0_SysRef_FPGA_N, PCIE0_SysRef_FPGA_P, PCIE1_SysRef_FPGA_N, PCIE1_SysRef_FPGA_P, PCIE2_SysRef_FPGA_N, PCIE2_SysRef_FPGA_P, PCIE3_SysRef_FPGA_N, PCIE3_SysRef_FPGA_P, PCIE4_SysRef_FPGA_N, PCIE4_SysRef_FPGA_P
net class PCIE3_SysRef_FPGA: PCIE0_SysRef_FPGA_N, PCIE0_SysRef_FPGA_P, PCIE1_SysRef_FPGA_N, PCIE1_SysRef_FPGA_P, PCIE2_SysRef_FPGA_N, PCIE2_SysRef_FPGA_P, PCIE3_SysRef_FPGA_N, PCIE3_SysRef_FPGA_P, PCIE4_SysRef_FPGA_N, PCIE4_SysRef_FPGA_P
net class PCIE4_SysRef_FPGA: PCIE0_SysRef_FPGA_N, PCIE0_SysRef_FPGA_P, PCIE1_SysRef_FPGA_N, PCIE1_SysRef_FPGA_P, PCIE2_SysRef_FPGA_N, PCIE2_SysRef_FPGA_P, PCIE3_SysRef_FPGA_N, PCIE3_SysRef_FPGA_P, PCIE4_SysRef_FPGA_N, PCIE4_SysRef_FPGA_P

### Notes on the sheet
- RDIV=2
- Fvco=2000MHz
- NDIV=8
- Fvref=500MHz
- LVPECL
- 8V !
- Zamieniona polaryzacja
- Cmos stan wysoki od 1.5V - 3.3V
- Podłączyć zasilanie

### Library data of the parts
C45 = Capacitor: Cap Ceramic 0.0056uF 25V X7R 10% SMD 0402 125C Paper T/R; Manufacturer: Yageo; Manufacturer Part Number: CC0402KRX7R8BB562
C46 = Capacitor: Multilayer Ceramic Capacitors MLCC - SMD/SMT 200pF 50V NPO 5%; Manufacturer: Yageo; Manufacturer Part Number: CC0402JRNPO9BN201
C334 C335 = Capacitor: as C588 on sheet WR_Clock
R77 = Resistor: RES SMD 7.5K OHM 0.5% 1/16W 0402; Manufacturer: Susumu; Manufacturer Part Number: RR0510P-752-D; Power Rating: 62.5mW; Voltage Rating: 25V; Max Power Dissipation: 63mW; Temperature Coefficient: 25ppm/°C; Voltage Rating (DC): 50V
R532 = Resistor: Res Thick Film 0402 75 Ohm 1% 1/10W 100ppm/C Molded SMD SMD Punched Carrier T/R; Manufacturer: Panasonic; Manufacturer Part Number: ERJ-2RKF75R0X; Voltage Rating: 50V; Power Rating: 100mW; Temperature Coefficient: 100ppm/°C
R533 = Resistor: RES SMD 30 OHM 0.5% 1/16W 0402; Manufacturer: Panasonic; Manufacturer Part Number: ERA-2AKD300X; Power Rating: 62.5mW; Temperature Coefficient: 100ppm/°C; Max Power Dissipation: 63mW
TP19 TP20 = TestPoint: Manufacturer: Keystone Electronics; Manufacturer Part Number: 5001; Plating: Silver; Body Material: PBT,Bronze; Number of Ports: 1; Insulation: Insulated; Inside Diameter: 1.27mm; Outside Diameter: 2.54mm; Hole Diameter: 1.6mm
X1 = CVCO55CC-2000-2000: Manufacturer: Crystek; Frequency: 2GHz; Load Capacitance: 22pF; Operating Supply Voltage: 8V

## Sheet DAC.SchDoc: DAC
size A4; Organization: Altium Limited; Address1: L3, 12a Rodborough Rd; Address2: Frenchs Forest; Address3: NSW; Address4: Australia 2086
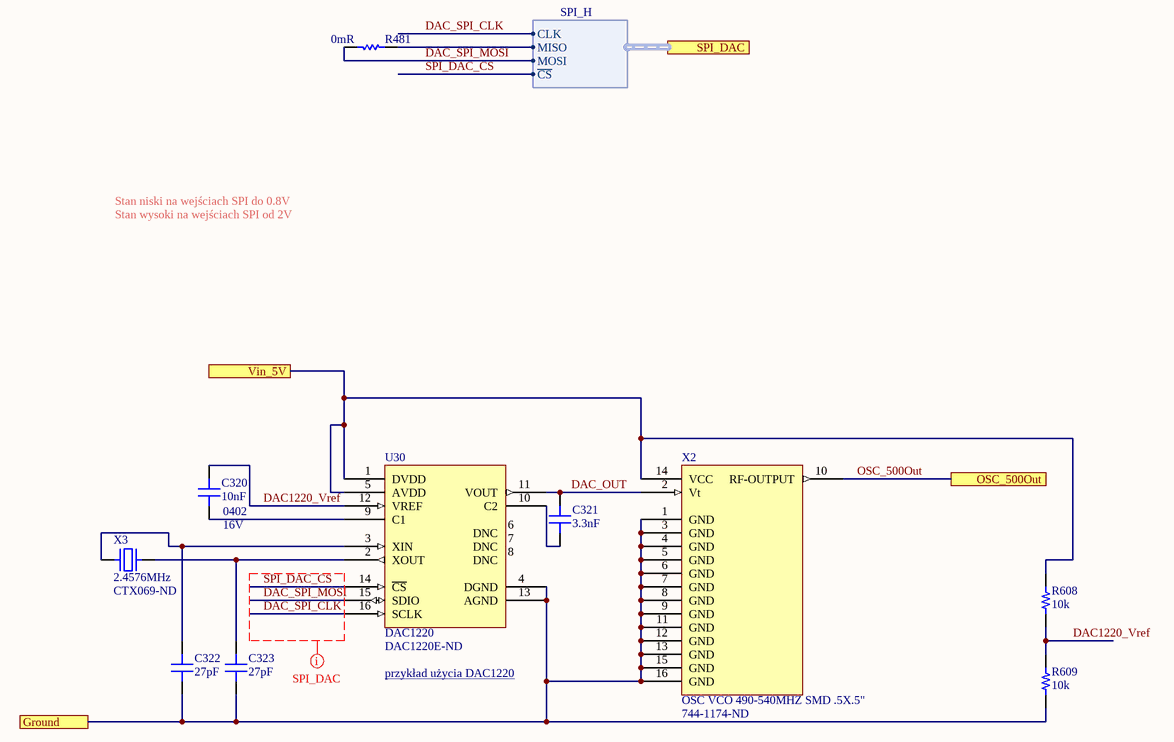
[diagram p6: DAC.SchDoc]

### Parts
C320  10nF  Case/Package: 0402  Voltage Rating (DC): 16V  [CAP 0402/1005 KK]
C321  3.3nF  [CAP 0603/1608 RF]
C322  27pF  [CAP 0402/1005 KK]
C323  27pF  [CAP 0402/1005 KK]
R481  0mR  [RES 0402/1005 RF KK]
R608  10k  [RES 0402/1005 RF KK]
R609  10k  [RES 0402/1005 RF KK]
U30  DAC1220  Supplier Part Number 1: DAC1220E-ND  [DAC1220]
X2  OSC VCO 490-540MHZ SMD .5X.5"  Supplier Part Number 1: 744-1174-ND  [CVCO55CW]
X3  2.4576MHz  Supplier Part Number 1: CTX069-ND  [Crystal]

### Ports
Ground, OSC_500Out, SPI_DAC (harness SPI_H), Vin_5V

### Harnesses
SPI_H: CLK, MISO, MOSI, ~{CS}

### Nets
5V_LN: R608.1 U30.1(DVDD) U30.5(AVDD) X2.14(VCC) ; port Vin_5V
AGND: C322.1 C323.1 R609.2 U30.4(DGND) U30.13(AGND) X2.1(GND) X2.3(GND) X2.4(GND) X2.5(GND) X2.6(GND) X2.7(GND) X2.8(GND) X2.9(GND) X2.11(GND) X2.12(GND) X2.13(GND) X2.15(GND) X2.16(GND) ; port Ground
DAC1220_Vref: C320.1 R608.2 R609.1 U30.12(VREF)
DAC_OUT: C321.2 U30.11(VOUT) X2.2(Vt)
DAC_SPI_CLK: U30.16(SCLK) ; port SPI_DAC.CLK
DAC_SPI_MOSI: R481.1 U30.15(SDIO) ; port SPI_DAC.MOSI
OSC_500Out: X2.10(RF-OUTPUT) ; port OSC_500Out
SPI_DAC_CS: U30.14(~{CS}) ; port SPI_DAC.~{CS}
NetC320_2: C320.2 U30.9(C1)
NetC321_1: C321.1 U30.10(C2)
NetC322_2: C322.2 U30.3(XIN) X3.1
NetC323_2: C323.2 U30.2(XOUT) X3.2
NetR481_2: R481.2 ; port SPI_DAC.MISO

Not connected (* = marked no-connect by the designer): U30 6(DNC) 7(DNC) 8(DNC)

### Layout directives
net class SPI_DAC: DAC_SPI_CLK, DAC_SPI_MOSI, SPI_DAC_CS

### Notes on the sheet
- Stan niski na wejściach SPI do 0.8V
- Stan wysoki na wejściach SPI od 2V
- przykład użycia DAC1220 <http://www.ti.com/lit/ug/sbau102/sbau102.pdf>

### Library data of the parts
C320 = Capacitor: Manufacturer: KEMET; Manufacturer Part Number: C0402C103K4RACTU; Dielectric Material: Ceramic; Tolerance: 10%; Dielectric: X7R; Dissipation Factor: 3.5%
C321 = Capacitor: Manufacturer: Wurth Electronics; Manufacturer Part Number: 885012006016; Voltage Rating: 10V; Tolerance: 5%
C322 C323 = Capacitor: Manufacturer: KEMET; Manufacturer Part Number: C0402C270K5GACTU; Dielectric Material: Ceramic; Tolerance: 10%; Voltage Rating (DC): 50V; Dielectric: C0G
R481 = Resistor: as R1095 on sheet LED_US_1
R608 R609 = Resistor: SMT Resistor
U30 = DAC1220: DAC 20bit; Manufacturer: Texas Instruments; Manufacturer Part Number: DAC1220E; Number of Bits: 20; Operating Supply Voltage: 5V; Interface: SPI; Resolution: 20b; Sampling Rate: 500S/s; Number of Channels: 1; Settling Time: 2000us; Output Type: Voltage; Max Supply Voltage: 5.25V; Min Supply Voltage: 4.75V; Power Consumption: 2.5mW; Nominal Supply Current: 460uA; Supply Type: Analog,Digital; Integral Nonlinearity (INL): 1LSB; Full Scale Error: 10LSB; Polarity: Unipolar
X2 = CVCO55CL-0490-0540: Manufacturer: Crystek; Frequency: 540MHz; Load Capacitance: 100pF; Max Supply Voltage: 5.25V; Min Supply Voltage: 4.75V
X3 = MP024S: CRYSTAL 2.4576MHZ 32PF T/H; Manufacturer: CTS; Frequency Tolerance: 30ppm; Frequency Stability: 50ppm; ESR (Equivalent Series Resistance): 300R

## Sheet CLK_Mux.SchDoc: Selektor zegarów
size A3; Organization: Altium Limited; Address1: L3, 12a Rodborough Rd; Address2: Frenchs Forest; Address3: NSW; Address4: Australia 2086
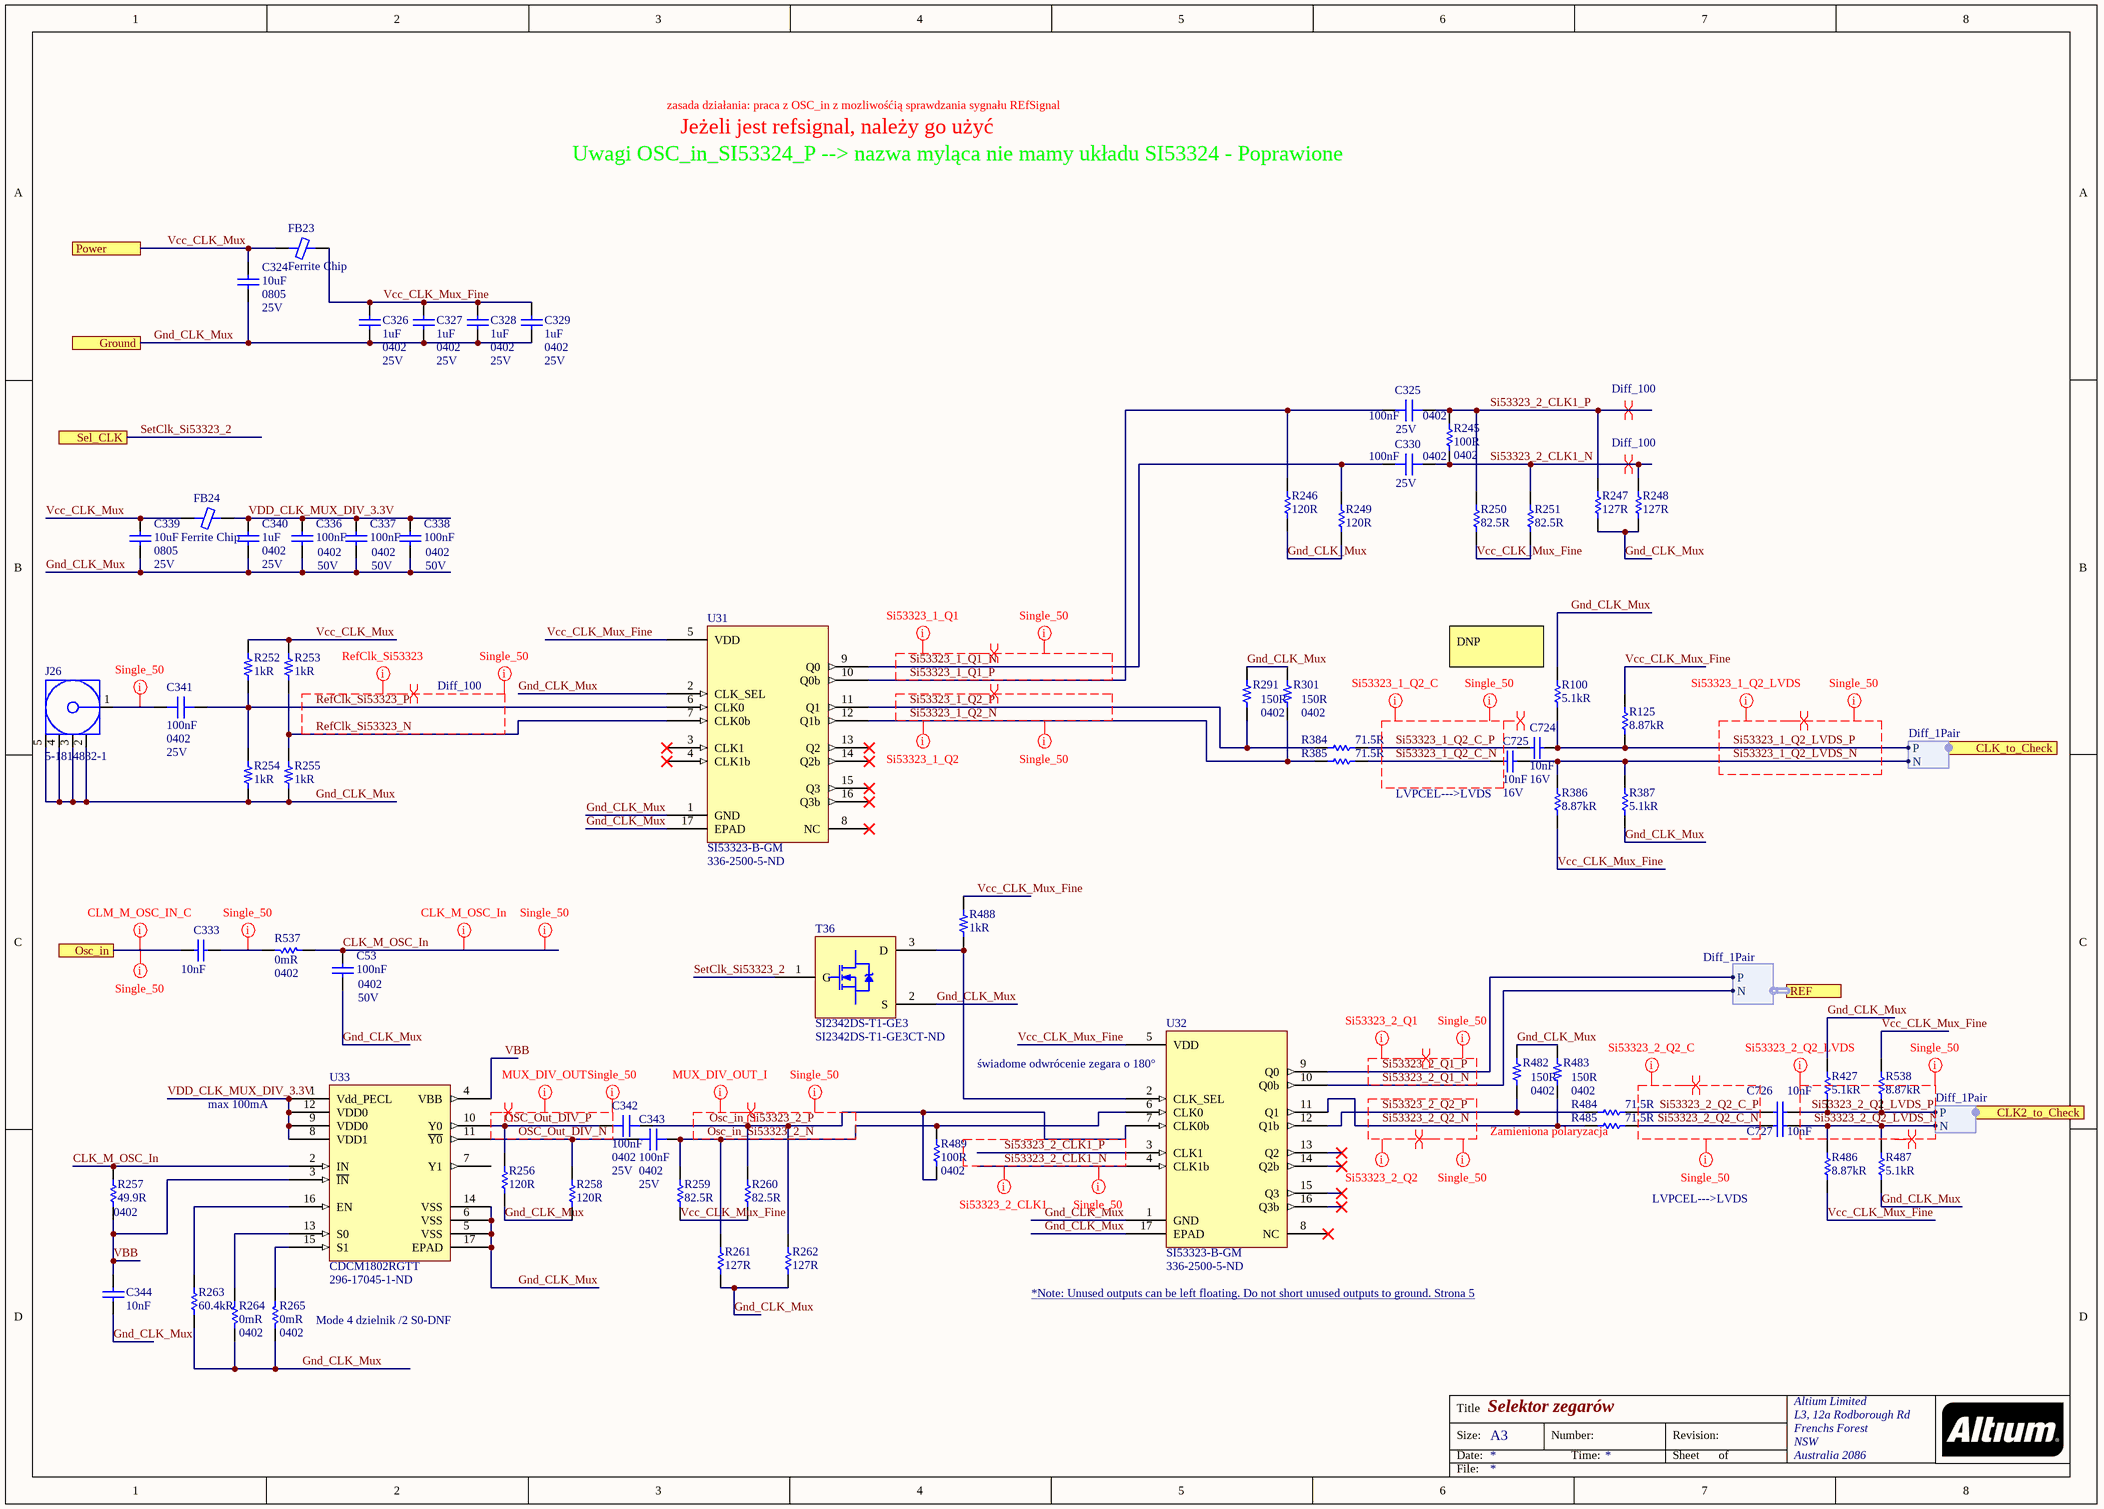
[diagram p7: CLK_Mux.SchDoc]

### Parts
C53  100nF  Case Code (Imperial): 0402  Voltage: 50V  [CAP 0402/1005 KK]
C324  10uF  Case/Package: 0805  Voltage Rating: 25V  [CAP 0805/2012 RF]
C325  100nF  Case/Package: 0402  Voltage Rating: 25V  [CAP 0402/1005 KK]
C326  1uF  Case/Package: 0402  Voltage Rating: 25V  [CAP 0402/1005 KK]
C327  1uF  Case/Package: 0402  Voltage Rating: 25V  [CAP 0402/1005 KK]
C328  1uF  Case/Package: 0402  Voltage Rating: 25V  [CAP 0402/1005 KK]
C329  1uF  Case/Package: 0402  Voltage Rating: 25V  [CAP 0402/1005 KK]
C330  100nF  Case/Package: 0402  Voltage Rating: 25V  [CAP 0402/1005 KK]
C333  10nF  [CAP 0201/0603 KK]
C336  100nF  Case Code (Imperial): 0402  Voltage: 50V  [CAP 0402/1005 KK]
C337  100nF  Case Code (Imperial): 0402  Voltage: 50V  [CAP 0402/1005 KK]
C338  100nF  Case Code (Imperial): 0402  Voltage: 50V  [CAP 0402/1005 KK]
C339  10uF  Case/Package: 0805  Voltage Rating: 25V  [CAP 0805/2012 RF]
C340  1uF  Case/Package: 0402  Voltage Rating: 25V  [CAP 0402/1005 KK]
C341  100nF  Case/Package: 0402  Voltage Rating: 25V  [CAP 0402/1005 KK]
C342  100nF  Case/Package: 0402  Voltage Rating: 25V  [CAP 0402/1005 KK]
C343  100nF  Case/Package: 0402  Voltage Rating: 25V  [CAP 0402/1005 KK]
C344  10nF  [CAP 0201/0603 KK]
C724  10nF  Voltage Rating (DC): 16V  [CAP 0201/0603 KK]
C725  10nF  Voltage Rating (DC): 16V  [CAP 0201/0603 KK]
C726  10nF  [CAP 0201/0603 KK]
C727  10nF  [CAP 0201/0603 KK]
FB23  Ferrite Chip  [FER 0603/1608]
FB24  Ferrite Chip  [FER 0603/1608]
J26  5-1814832-1  [TECO-5-1814832-1_V]
R100  5.1kR  [RES 0402/1005 RF KK]
R125  8.87kR  [RES 0402/1005 RF KK]
R245  100R  Case/Package: 0402  [RES 0402/1005 RF KK]
R246  120R  [RES 0402/1005 RF KK]
R247  127R  [RES 0402/1005 RF KK]
R248  127R  [RES 0402/1005 RF KK]
R249  120R  [RES 0402/1005 RF KK]
R250  82.5R  [RES 0402/1005 RF KK]
R251  82.5R  [RES 0402/1005 RF KK]
R252  1kR  [RES 0402/1005 RF KK]
R253  1kR  [RES 0402/1005 RF KK]
R254  1kR  [RES 0402/1005 RF KK]
R255  1kR  [RES 0402/1005 RF KK]
R256  120R  [RES 0402/1005 RF KK]
R257  49.9R  Case/Package: 0402  [RES 0402/1005 RF KK]
R258  120R  [RES 0402/1005 RF KK]
R259  82.5R  [RES 0402/1005 RF KK]
R260  82.5R  [RES 0402/1005 RF KK]
R261  127R  [RES 0402/1005 RF KK]
R262  127R  [RES 0402/1005 RF KK]
R263  60.4kR  [RES 0402/1005 RF KK]
R264  0mR  Case/Package: 0402  [RES 0402/1005 RF KK]
R265  0mR  Case/Package: 0402  [RES 0402/1005 RF KK]
R291  150R  Case/Package: 0402  [RES 0402/1005 RF KK]
R301  150R  Case/Package: 0402  [RES 0402/1005 RF KK]
R384  71.5R  [RES 0402/1005 RF KK]
R385  71.5R  [RES 0402/1005 RF KK]
R386  8.87kR  [RES 0402/1005 RF KK]
R387  5.1kR  [RES 0402/1005 RF KK]
R427  5.1kR  [RES 0402/1005 RF KK]
R482  150R  Case/Package: 0402  [RES 0402/1005 RF KK]
R483  150R  Case/Package: 0402  [RES 0402/1005 RF KK]
R484  71.5R  [RES 0402/1005 RF KK]
R485  71.5R  [RES 0402/1005 RF KK]
R486  8.87kR  [RES 0402/1005 RF KK]
R487  5.1kR  [RES 0402/1005 RF KK]
R488  1kR  [RES 0402/1005 RF KK]
R489  100R  Case/Package: 0402  [RES 0402/1005 RF KK]
R537  0mR  Case/Package: 0402  [RES 0402/1005 RF KK]
R538  8.87kR  [RES 0402/1005 RF KK]
T36  SI2342DS-T1-GE3  Supplier Part Number 1: SI2342DS-T1-GE3CT-ND  [SI2342DS-T1-GE3]
U31  SI53323-B-GM  Supplier Part Number 1: 336-2500-5-ND  [SI53323-B-GM]
U32  SI53323-B-GM  Supplier Part Number 1: 336-2500-5-ND  [SI53323-B-GM]
U33  CDCM1802RGTT  Supplier Part Number 1: 296-17045-1-ND  [CDCM1802RGTT]

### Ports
CLK2_to_Check (harness Diff_1Pair), CLK_to_Check (harness Diff_1Pair), Ground, Osc_in, Power, REF (harness Diff_1Pair), Sel_CLK

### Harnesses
Diff_1Pair: P, N
Diff_1Pair: N, P

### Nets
CLK_M_OSC_In: C53.2 R257.2 R537.1 U33.2(IN)
Gnd_CLK_Mux: C53.1 C324.1 C326.2 C327.2 C328.2 C329.2 C336.1 C337.1 C338.1 C339.1 C340.2 C344.1 J26.2 J26.3 J26.4 J26.5 R100.1 R246.1 R247.1 R248.1 R249.2 R254.1 R255.1 R256.1 R258.2 R261.1 R262.1 R263.1 R264.1 R265.1 R291.2 R301.2 R387.1 R427.1 R482.2 R483.2 R487.1 T36.2(S) U31.1(GND) U31.2(CLK_SEL) U31.17(EPAD) U32.1(GND) U32.17(EPAD) U33.5(VSS) U33.6(VSS) U33.14(VSS) U33.17(EPAD) ; port Ground  [project net AGND]
OSC_500Out: C333.1 ; port Osc_in
Osc_in_Si53323_2_N: C343.1 R259.2 R261.2 R489.2 U32.6(CLK0)
Osc_in_Si53323_2_P: C342.1 R260.2 R262.2 R489.1 U32.7(CLK0b)
OSC_Out_DIV_N: C343.2 R258.1 U33.11(~{Y0})
OSC_Out_DIV_P: C342.2 R256.2 U33.10(Y0)
RefClk_Si53323_N: R253.1 R255.2 U31.7(CLK0b)
RefClk_Si53323_P: C341.1 R252.1 R254.2 U31.6(CLK0)
SetClk_Si53323_2: T36.1(G) ; port Sel_CLK
Si53323_1_Q1_N: C330.2 R249.1 U31.9(Q0)
Si53323_1_Q1_P: C325.2 R246.2 U31.10(Q0b)
Si53323_1_Q2_C_N: C725.2 R385.1
Si53323_1_Q2_C_P: C724.2 R384.1
Si53323_1_Q2_LVDS_N: C725.1 R386.2 R387.2 ; port CLK_to_Check.N
Si53323_1_Q2_LVDS_P: C724.1 R100.2 R125.2 ; port CLK_to_Check.P
Si53323_1_Q2_N: R301.1 R385.2 U31.12(Q1b)
Si53323_1_Q2_P: R291.1 R384.2 U31.11(Q1)
Si53323_2_CLK1_N: C330.1 R245.1 R248.2 R251.2 U32.4(CLK1b)
Si53323_2_CLK1_P: C325.1 R245.2 R247.2 R250.2 U32.3(CLK1)
Si53323_2_Q1_N: U32.10(Q0b) ; port REF.N
Si53323_2_Q1_P: U32.9(Q0) ; port REF.P
Si53323_2_Q2_C_N: C727.2 R485.1
Si53323_2_Q2_C_P: C726.2 R484.1
Si53323_2_Q2_LVDS_N: C727.1 R486.2 R487.2 ; port CLK2_to_Check.N
Si53323_2_Q2_LVDS_P: C726.1 R427.2 R538.2 ; port CLK2_to_Check.P
Si53323_2_Q2_N: R483.1 R485.2 U32.11(Q1)
Si53323_2_Q2_P: R482.1 R484.2 U32.12(Q1b)
VBB: C344.2 R257.1 U33.3(~{IN}) U33.4(VBB)
Vcc_CLK_Mux: C324.2 C339.2 FB23.1 FB24.1 R252.2 R253.2 ; port Power  [project net 3V3_RAIL]
Vcc_CLK_Mux_Fine: C326.1 C327.1 C328.1 C329.1 FB23.2 R125.1 R250.1 R251.1 R259.1 R260.1 R386.1 R486.1 R488.2 R538.1 U31.5(VDD) U32.5(VDD)
VDD_CLK_MUX_DIV_3.3V: C336.2 C337.2 C338.2 C340.1 FB24.2 U33.1(Vdd_PECL) U33.8(VDD1) U33.9(VDD0) U33.12(VDD0)
NetC333_2: C333.2 R537.2
NetC341_2: C341.2 J26.1
NetR263_2: R263.2 U33.16(EN)
NetR264_2: R264.2 U33.13(S0)
NetR265_2: R265.2 U33.15(S1)
NetR488_1: R488.1 T36.3(D) U32.2(CLK_SEL)

Not connected (* = marked no-connect by the designer): U31 3(CLK1)* 4(CLK1b)* 8(NC)* 13(Q2)* 14(Q2b)* 15(Q3)* 16(Q3b)*; U32 8(NC)* 13(Q2)* 14(Q2b)* 15(Q3)* 16(Q3b)*; U33 7(Y1)

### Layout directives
differential pair; differential pair class Diff_100: Osc_in_Si53323_2_N, Osc_in_Si53323_2_P, OSC_Out_DIV_N, OSC_Out_DIV_P, RefClk_Si53323_N, RefClk_Si53323_P, Si53323_1_Q1_N, Si53323_1_Q1_P, Si53323_1_Q2_C_N, Si53323_1_Q2_C_P, Si53323_1_Q2_LVDS_N, Si53323_1_Q2_LVDS_P, Si53323_1_Q2_N, Si53323_1_Q2_P, Si53323_2_CLK1_N, Si53323_2_CLK1_P, Si53323_2_Q1_N, Si53323_2_Q1_P, Si53323_2_Q2_C_N, Si53323_2_Q2_C_P, Si53323_2_Q2_LVDS_N, Si53323_2_Q2_LVDS_P, Si53323_2_Q2_N, Si53323_2_Q2_P
net class MUX_DIV_OUT_I: Osc_in_Si53323_2_N, Osc_in_Si53323_2_P
net class CLM_M_OSC_IN_C: OSC_500Out
net class Si53323_2_Q1: Si53323_2_Q1_N, Si53323_2_Q1_P
net class Si53323_2_Q2: Si53323_2_Q2_N, Si53323_2_Q2_P
net class Si53323_1_Q1: Si53323_1_Q1_N, Si53323_1_Q1_P
net class Si53323_1_Q2: Si53323_1_Q2_N
net class CLK_M_OSC_In: CLK_M_OSC_In
net class Single_50: CLK_M_OSC_In, NetC333_2, NetC341_2, OSC_500Out, Osc_in_Si53323_2_N, Osc_in_Si53323_2_P, OSC_Out_DIV_N, OSC_Out_DIV_P, RefClk_Si53323_N, RefClk_Si53323_P, Si53323_1_Q1_N, Si53323_1_Q1_P, Si53323_1_Q2_C_N, Si53323_1_Q2_C_P, Si53323_1_Q2_LVDS_N, Si53323_1_Q2_LVDS_P, Si53323_1_Q2_N, Si53323_2_CLK1_N, Si53323_2_Q1_N, Si53323_2_Q1_P, Si53323_2_Q2_C_N, Si53323_2_Q2_C_P, Si53323_2_Q2_LVDS_N, Si53323_2_Q2_LVDS_P, Si53323_2_Q2_N, Si53323_2_Q2_P
net class MUX_DIV_OUT: OSC_Out_DIV_N, OSC_Out_DIV_P
net class Si53323_2_CLK1: Si53323_2_CLK1_N
net class RefClk_Si53323: RefClk_Si53323_N, RefClk_Si53323_P
net class Si53323_1_Q2_LVDS: Si53323_1_Q2_LVDS_N, Si53323_1_Q2_LVDS_P
net class Si53323_2_Q2_LVDS: Si53323_2_Q2_LVDS_N, Si53323_2_Q2_LVDS_P
net class Si53323_1_Q2_C: Si53323_1_Q2_C_N, Si53323_1_Q2_C_P
net class Si53323_2_Q2_C: Si53323_2_Q2_C_N, Si53323_2_Q2_C_P

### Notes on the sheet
- zasada działania: praca z OSC_in z mozliwośćią sprawdzania sygnału REfSignal
- Uwagi OSC_in_SI53324_P --> nazwa myląca nie mamy układu SI53324 - Poprawione
- Jeżeli jest refsignal, należy go użyć
- (near R100) DNP
- LVPCEL--->LVDS
- max 100mA
- (near U32) świadome odwrócenie zegara o 180°
- (near R485) Zamieniona polaryzacja
- (near R265) Mode 4 dzielnik /2 S0-DNF
- *Note: Unused outputs can be left floating. Do not short unused outputs to ground. Strona 5 <https://datasheet.ciiva.com/24019/si53323-258666-24019274.pdf?src-supplier=Mouser>

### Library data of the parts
C53 C336-C338 = Capacitor: as C590 on sheet WR_Clock
C324 C339 = Capacitor: CAP CER 10UF 25V X5R 0805; Manufacturer: KEMET; Manufacturer Part Number: C0805C106K3PACTU; Dielectric Material: Ceramic; Dissipation Factor: 10%
C325 C330 C341-C343 = Capacitor: as C588 on sheet WR_Clock
C326-C329 C340 = Capacitor: MURATA - GRT155R61E105KE01D - SMD Multilayer Ceramic Capacitor, 1 µF, 25 V, 0402 [1005 Metric], ± 10%, X5R, GRT Series - SMD Multilayer Ceramic Capacitor, 1 µF, 25 V, 0402 [1005 Metric], ± 10%, X5R, GRT Series
C333 C344 C724-C727 = Capacitor: CAP CER 10000PF 16V X7R 0201; Manufacturer: Murata; Manufacturer Part Number: GRM033R71C103KE14D; Tolerance: 10%
FB23 FB24 = Ferrite Chip: SMT Ferrite Chip; Manufacturer: TDK; Manufacturer Part Number: MPZ1608S331ATA00; Tolerance: 25%; Impedance: 330R; DC Resistance (DCR): 80mR; Max DC Current: 1.7A
J26 = 5-1814832-1: SMA Connector, Pitch 5.08 mm, 1 Position, Height 9.5 mm, Tail Length 4 mm, -65 to 165 degC, RoHS, Bulk; SVHC: No SVHC (15-Jun-2015); Connector Mounting: PCB Mount; Coaxial Termination: Solder; Frequency Max: 3GHz; Product Range: ZDC Series; Connector Type: SMA Coaxial; Connector Body Style: Straight Jack; Impedance: 50ohm
R100 R387 R427 R487 = Resistor: Manufacturer: Panasonic; Manufacturer Part Number: ERJ-2RKF5101X; Temperature Coefficient: 100ppm/°C; Tolerance: 1%; Power Rating: 100mW; Voltage Rating: 50V
R125 R386 R486 R538 = Resistor: Manufacturer: Stackpole Electronics; Manufacturer Part Number: RMCF0402FT8K87; Tolerance: 1%; Max Power Dissipation: 63mW; Temperature Coefficient: 100ppm/°C
R245 R489 = Resistor: as R311 on sheet WR_Clock
R246 R249 R256 R258 = Resistor: Res Thin Film 0402 120 Ohm 0.5% 1/16W ±25ppm/C Molded SMD Punched Carrier T/R; Manufacturer: Panasonic; Manufacturer Part Number: ERA-2AED121X; Power Rating: 63mW; Voltage Rating: 25V; Temperature Coefficient: 25ppm/°C
R247 R248 R261 R262 = Resistor: Res Thick Film 0402 127 Ohm 1% 0.063W(1/16W) }100ppm/? Molded SMD Paper T/R; Manufacturer: Yageo; Manufacturer Part Number: RC0402FR-07127RL; Voltage Rating: 50V; Power Rating: 62.5mW; Max Power Dissipation: 63mW; Temperature Coefficient: 100ppm/°C
R250 R251 R259 R260 = Resistor: Res Thick Film 0402 82.5 Ohm 1% 0.063W(1/16W) ±100ppm/C Molded SMD Automotive Punched Paper T/R; Manufacturer: KOA Speer; Manufacturer Part Number: RK73H1ETTP82R5F; Power Rating: 63mW; Voltage Rating: 50V; Temperature Coefficient: 100ppm/°C
R252-R255 R488 = Resistor: as R499 on sheet WR_Clock
R257 = Resistor: as R545 on sheet WR_Clock
R263 = Resistor: RES 60.4K OHM 1% 1/16W 0402; Manufacturer: Stackpole Electronics; Manufacturer Part Number: RMCF0402FT60K4; Max Power Dissipation: 63mW; Temperature Coefficient: 100ppm/°C
R264 R265 R537 = Resistor: as R1095 on sheet LED_US_1
R291 R301 R482 R483 = Resistor: RES SMD 150 OHM 1% 1/10W 0402; Manufacturer: Panasonic; Manufacturer Part Number: ERJ-2RKF1500X; Temperature Coefficient: 100ppm/°C; Power Rating: 100mW; Voltage Rating: 50V
R384 R385 R484 R485 = Resistor: Manufacturer: Vishay; Manufacturer Part Number: CRCW040271R5FKED; Max Power Dissipation: 63mW; Voltage Rating (DC): 50V; Tolerance: 1%; Temperature Coefficient: 100ppm/°C
T36 = SI2342DS-T1-GE3: as T50 on sheet LED_US_1
U31 U32 = SI53323-B-GM: IC BUFFER 2:4 LVPECL MUX 16QFN; Manufacturer 1: Silicon Labs; Max Supply Voltage: 3.63V; Min Supply Voltage: 2.38V; Propagation Delay: 0.975ns; Number of Outputs: 4; Frequency: 1.25GHz; Nominal Supply Current: 210mA; Number of Circuits: 1; Max Duty Cycle: 54%; Logic Function: Clock; Input: LVCMOS
U33 = CDCM1802RGTT: IC, BUF LVPECL CLOCK DRVR 16-VQFN; Manufacturer: Texas Instruments; Frequency: 800MHz; Number of Outputs: 1; Min Supply Voltage: 3V; Max Supply Voltage: 3.6V; Nominal Supply Current: 10uA; Propagation Delay: 600ps; Logic Function: Buffer,Clock; Input: LVTTL

## Sheet LTC6952_1.SchDoc
size A3
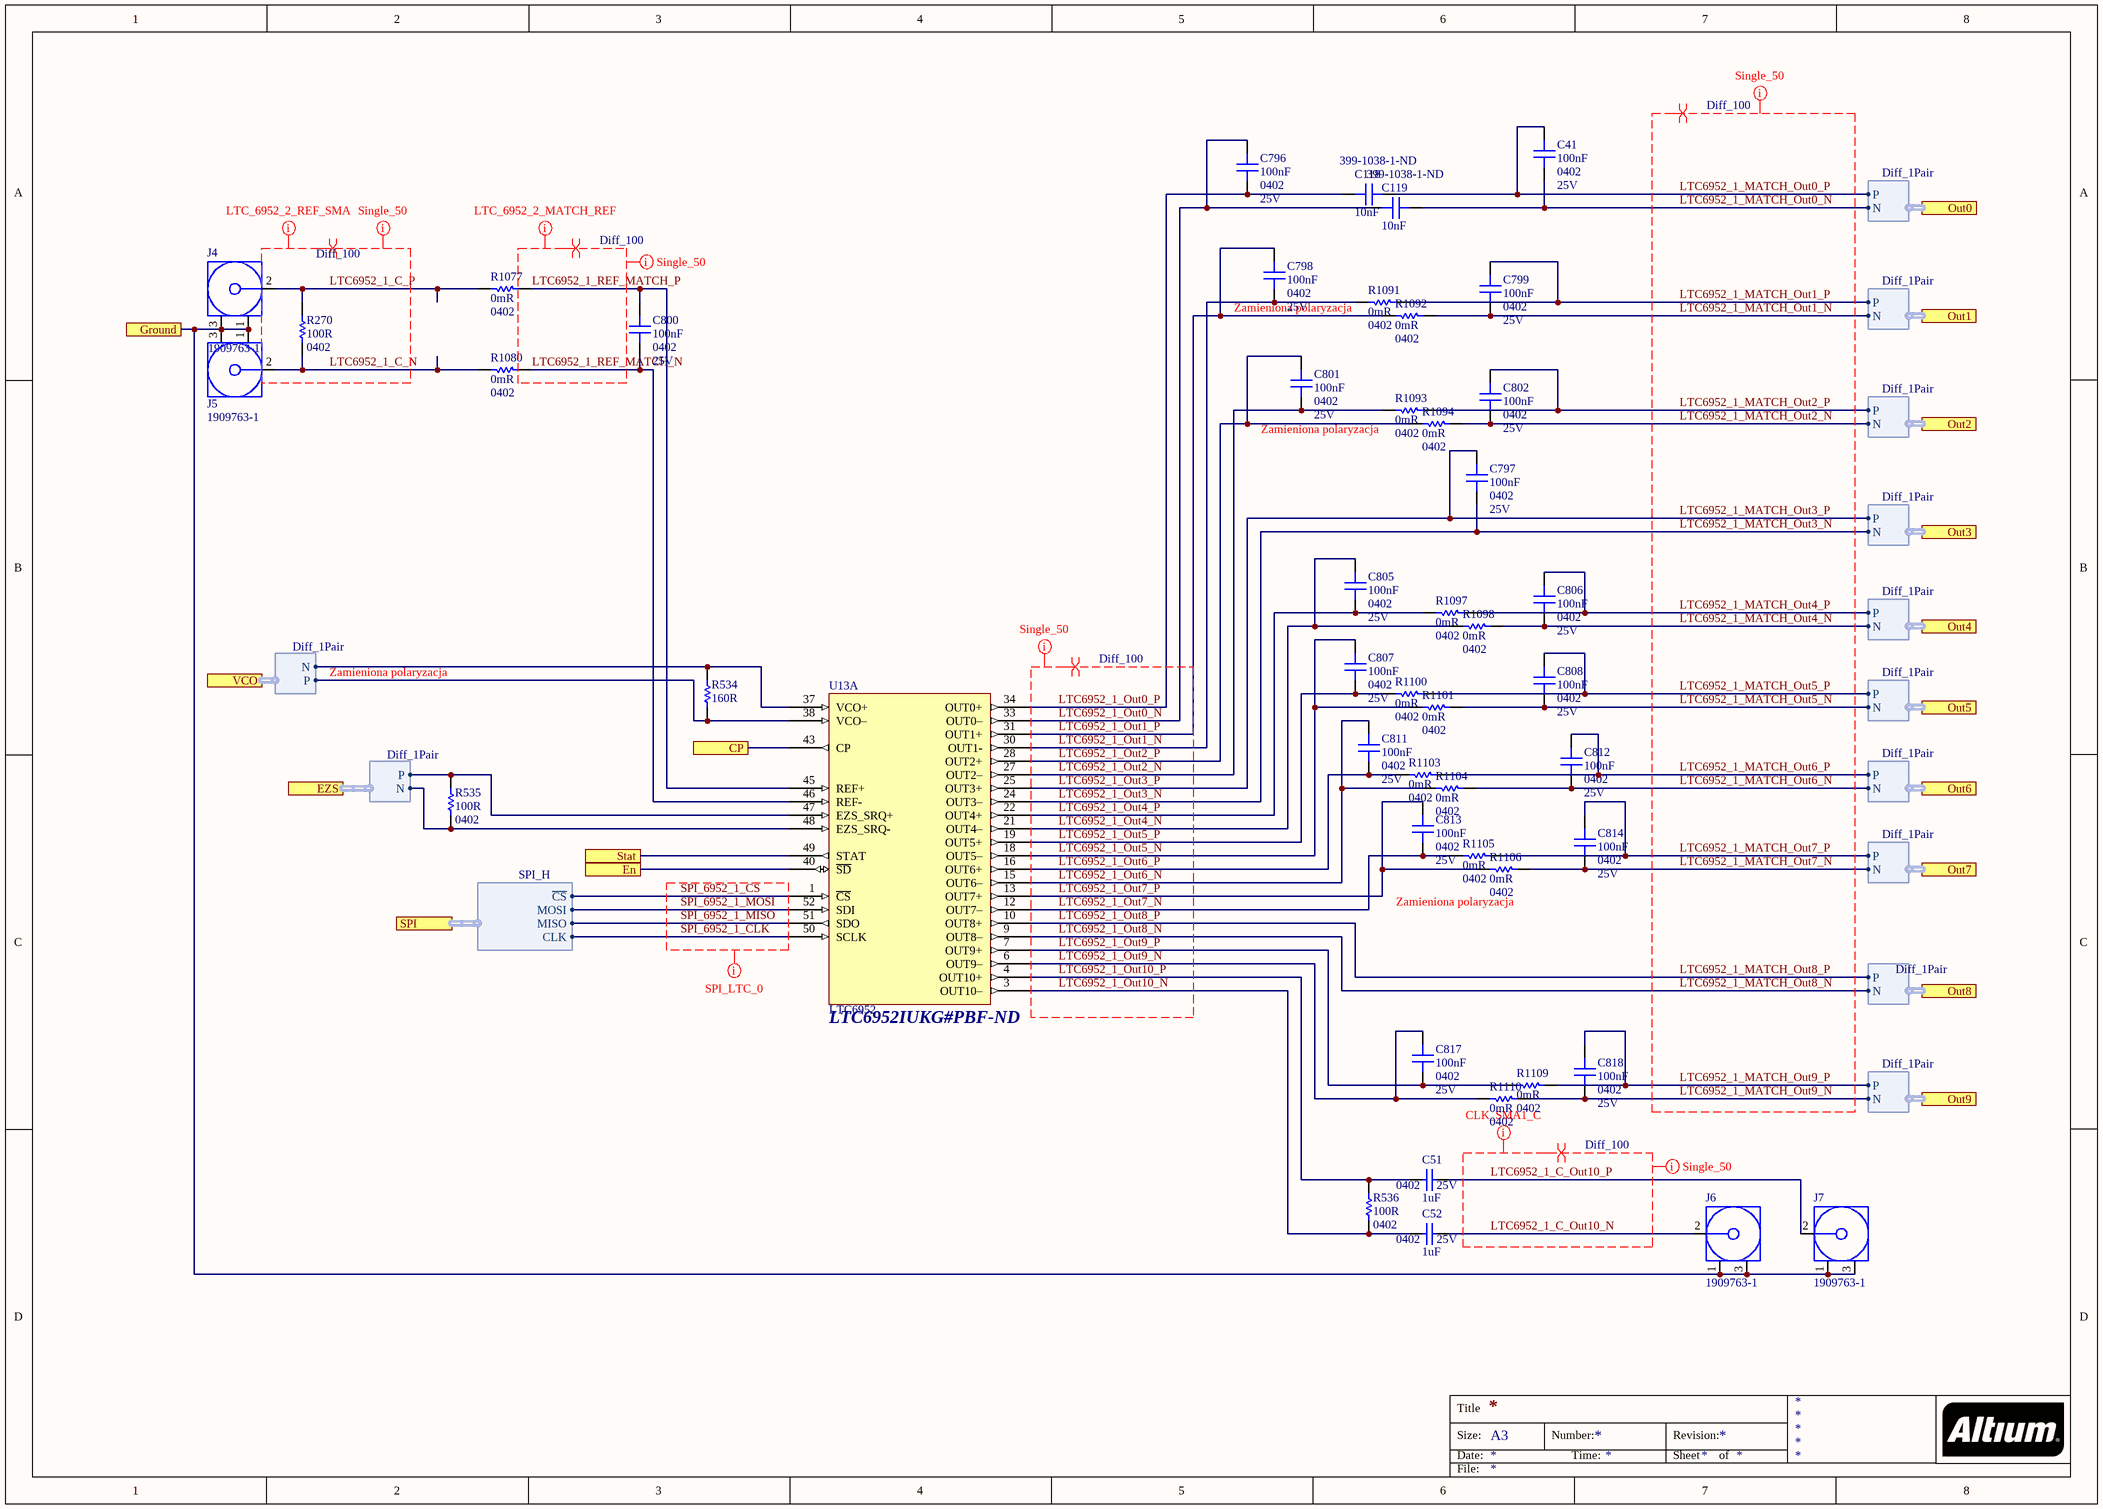
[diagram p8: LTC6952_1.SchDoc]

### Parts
(Parts that share a designator on the sheet are numbered #1, #2 ... from top to bottom, then left to right.)
C41  100nF  Case/Package: 0402  Voltage Rating: 25V  [CAP 0402/1005 KK]
C51  1uF  Case/Package: 0402  Voltage Rating: 25V  [CAP 0402/1005 KK]
C52  1uF  Case/Package: 0402  Voltage Rating: 25V  [CAP 0402/1005 KK]
C118#1  10nF  Supplier Part Number 1: 399-1038-1-ND  [CAP 0402/1005 KK]
C119#1  10nF  Supplier Part Number 1: 399-1038-1-ND  [CAP 0402/1005 KK]
C796  100nF  Case/Package: 0402  Voltage Rating: 25V  [CAP 0402/1005 KK]
C797  100nF  Case/Package: 0402  Voltage Rating: 25V  [CAP 0402/1005 KK]
C798  100nF  Case/Package: 0402  Voltage Rating: 25V  [CAP 0402/1005 KK]
C799  100nF  Case/Package: 0402  Voltage Rating: 25V  [CAP 0402/1005 KK]
C800  100nF  Case/Package: 0402  Voltage Rating: 25V  [CAP 0402/1005 KK]
C801  100nF  Case/Package: 0402  Voltage Rating: 25V  [CAP 0402/1005 KK]
C802  100nF  Case/Package: 0402  Voltage Rating: 25V  [CAP 0402/1005 KK]
C805  100nF  Case/Package: 0402  Voltage Rating: 25V  [CAP 0402/1005 KK]
C806  100nF  Case/Package: 0402  Voltage Rating: 25V  [CAP 0402/1005 KK]
C807  100nF  Case/Package: 0402  Voltage Rating: 25V  [CAP 0402/1005 KK]
C808  100nF  Case/Package: 0402  Voltage Rating: 25V  [CAP 0402/1005 KK]
C811  100nF  Case/Package: 0402  Voltage Rating: 25V  [CAP 0402/1005 KK]
C812  100nF  Case/Package: 0402  Voltage Rating: 25V  [CAP 0402/1005 KK]
C813  100nF  Case/Package: 0402  Voltage Rating: 25V  [CAP 0402/1005 KK]
C814  100nF  Case/Package: 0402  Voltage Rating: 25V  [CAP 0402/1005 KK]
C817  100nF  Case/Package: 0402  Voltage Rating: 25V  [CAP 0402/1005 KK]
C818  100nF  Case/Package: 0402  Voltage Rating: 25V  [CAP 0402/1005 KK]
J4  1909763-1  [TECO-1909763-1_V]
J5  1909763-1  [TECO-1909763-1_V]
J6  1909763-1  [TECO-1909763-1_V]
J7  1909763-1  [TECO-1909763-1_V]
R270  100R  Case/Package: 0402  [RES 0402/1005 RF KK]
R534  160R  [RES 0402/1005 RF KK]
R535  100R  Case/Package: 0402  [RES 0402/1005 RF KK]
R536  100R  Case/Package: 0402  [RES 0402/1005 RF KK]
R1077  0mR  Case/Package: 0402  [RES 0402/1005 RF KK]
R1080  0mR  Case/Package: 0402  [RES 0402/1005 RF KK]
R1091  0mR  Case/Package: 0402  [RES 0402/1005 RF KK]
R1092  0mR  Case/Package: 0402  [RES 0402/1005 RF KK]
R1093  0mR  Case/Package: 0402  [RES 0402/1005 RF KK]
R1094  0mR  Case/Package: 0402  [RES 0402/1005 RF KK]
R1097  0mR  Case/Package: 0402  [RES 0402/1005 RF KK]
R1098  0mR  Case/Package: 0402  [RES 0402/1005 RF KK]
R1100  0mR  Case/Package: 0402  [RES 0402/1005 RF KK]
R1101  0mR  Case/Package: 0402  [RES 0402/1005 RF KK]
R1103  0mR  Case/Package: 0402  [RES 0402/1005 RF KK]
R1104  0mR  Case/Package: 0402  [RES 0402/1005 RF KK]
R1105  0mR  Case/Package: 0402  [RES 0402/1005 RF KK]
R1106  0mR  Case/Package: 0402  [RES 0402/1005 RF KK]
R1109  0mR  Case/Package: 0402  [RES 0402/1005 RF KK]
R1110  0mR  Case/Package: 0402  [RES 0402/1005 RF KK]
U13  LTC6952  Supplier Part Number 1: LTC6952IUKG#PBF-ND  [LTC6952]  (part A of 2)

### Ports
CP, En, EZS (harness Diff_1Pair), Ground, Out0 (harness Diff_1Pair), Out1 (harness Diff_1Pair), Out2 (harness Diff_1Pair), Out3 (harness Diff_1Pair), Out4 (harness Diff_1Pair), Out5 (harness Diff_1Pair), Out6 (harness Diff_1Pair), Out7 (harness Diff_1Pair), Out8 (harness Diff_1Pair), Out9 (harness Diff_1Pair), SPI (harness SPI_H), Stat, VCO (harness Diff_1Pair)

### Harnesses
SPI_H: CLK, MISO, MOSI, ~{CS}
Diff_1Pair: N, P

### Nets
AGND: J4.1 J4.3 J5.1 J5.3 J6.1 J6.3 J7.1 J7.3 ; port Ground
Enable_CLK: U13.40(~{SD}) ; port En
LTC6952_0_MATCH_Out3_N: R535.1 U13.48(EZS_SRQ-) ; port EZS.N
LTC6952_0_MATCH_Out3_P: R535.2 U13.47(EZS_SRQ+) ; port EZS.P
LTC6952_0_MATCH_Out4_N: R534.2 U13.37(VCO+) ; port VCO.N
LTC6952_0_MATCH_Out4_P: R534.1 U13.38(VCO–) ; port VCO.P
LTC6952_1_C_N: J5.2 R270.1 R1080.2
LTC6952_1_C_Out10_N: C52.1 J6.2
LTC6952_1_C_Out10_P: C51.1 J7.2
LTC6952_1_C_P: J4.2 R270.2 R1077.2
LTC6952_1_MATCH_Out0_N: C41.2 C119#1.2 ; port Out0.N
LTC6952_1_MATCH_Out0_P: C41.1 C118#1.2 ; port Out0.P
LTC6952_1_MATCH_Out1_N: C799.2 R1092.1 ; port Out1.N
LTC6952_1_MATCH_Out1_P: C799.1 R1091.1 ; port Out1.P
LTC6952_1_MATCH_Out2_N: C802.2 R1094.1 ; port Out2.N
LTC6952_1_MATCH_Out2_P: C802.1 R1093.1 ; port Out2.P
LTC6952_1_MATCH_Out3_N: C797.2 U13.24(OUT3–) ; port Out3.N  [also labelled LTC6952_1_Out3_N]
LTC6952_1_MATCH_Out3_P: C797.1 U13.25(OUT3+) ; port Out3.P  [also labelled LTC6952_1_Out3_P]
LTC6952_1_MATCH_Out4_N: C806.2 R1098.1 ; port Out4.N
LTC6952_1_MATCH_Out4_P: C806.1 R1097.1 ; port Out4.P
LTC6952_1_MATCH_Out5_N: C808.2 R1101.1 ; port Out5.N
LTC6952_1_MATCH_Out5_P: C808.1 R1100.1 ; port Out5.P
LTC6952_1_MATCH_Out6_N: C812.2 R1104.1 ; port Out6.N
LTC6952_1_MATCH_Out6_P: C812.1 R1103.1 ; port Out6.P
LTC6952_1_MATCH_Out7_N: C814.2 R1106.1 ; port Out7.N
LTC6952_1_MATCH_Out7_P: C814.1 R1105.1 ; port Out7.P
LTC6952_1_MATCH_Out8_N: U13.9(OUT8–) ; port Out8.N  [also labelled LTC6952_1_Out8_N]
LTC6952_1_MATCH_Out8_P: U13.10(OUT8+) ; port Out8.P  [also labelled LTC6952_1_Out8_P]
LTC6952_1_MATCH_Out9_N: C818.2 R1110.1 ; port Out9.N
LTC6952_1_MATCH_Out9_P: C818.1 R1109.1 ; port Out9.P
LTC6952_1_Out0_N: C119#1.1 C796.1 U13.33(OUT0–)
LTC6952_1_Out0_P: C118#1.1 C796.2 U13.34(OUT0+)
LTC6952_1_Out1_N: C798.2 R1091.2 U13.30(OUT1-)
LTC6952_1_Out1_P: C798.1 R1092.2 U13.31(OUT1+)
LTC6952_1_Out2_N: C801.2 R1093.2 U13.27(OUT2–)
LTC6952_1_Out2_P: C801.1 R1094.2 U13.28(OUT2+)
LTC6952_1_Out4_N: C805.1 R1098.2 U13.21(OUT4–)
LTC6952_1_Out4_P: C805.2 R1097.2 U13.22(OUT4+)
LTC6952_1_Out5_N: C807.1 R1101.2 U13.18(OUT5–)
LTC6952_1_Out5_P: C807.2 R1100.2 U13.19(OUT5+)
LTC6952_1_Out6_N: C811.1 R1104.2 U13.15(OUT6–)
LTC6952_1_Out6_P: C811.2 R1103.2 U13.16(OUT6+)
LTC6952_1_Out7_N: C813.2 R1105.2 U13.12(OUT7–)
LTC6952_1_Out7_P: C813.1 R1106.2 U13.13(OUT7+)
LTC6952_1_Out9_N: C817.1 R1110.2 U13.6(OUT9–)
LTC6952_1_Out9_P: C817.2 R1109.2 U13.7(OUT9+)
LTC6952_1_Out10_N: C52.2 R536.1 U13.3(OUT10–)
LTC6952_1_Out10_P: C51.2 R536.2 U13.4(OUT10+)
LTC6952_1_REF_MATCH_N: C800.2 R1080.1 U13.46(REF-)
LTC6952_1_REF_MATCH_P: C800.1 R1077.1 U13.45(REF+)
LTC6952_2_Temp: U13.49(STAT) ; port Stat
SPI_6952_1_CLK: U13.50(SCLK) ; port SPI.CLK  [project net CLK1_SPI.CLK]
SPI_6952_1_CS: U13.1(~{CS}) ; port SPI.~{CS}  [project net CLK1_SPI.~{CS}]
SPI_6952_1_MISO: U13.51(SDO) ; port SPI.MISO  [project net CLK1_SPI.MISO]
SPI_6952_1_MOSI: U13.52(SDI) ; port SPI.MOSI  [project net CLK1_SPI.MOSI]
NetU13_43: U13.43(CP) ; port CP

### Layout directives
differential pair; differential pair class Diff_100: LTC6952_1_C_N, LTC6952_1_C_Out10_N, LTC6952_1_C_Out10_P, LTC6952_1_C_P, LTC6952_1_MATCH_Out0_N, LTC6952_1_MATCH_Out0_P, LTC6952_1_MATCH_Out1_N, LTC6952_1_MATCH_Out1_P, LTC6952_1_MATCH_Out2_N, LTC6952_1_MATCH_Out2_P, LTC6952_1_MATCH_Out3_N, LTC6952_1_MATCH_Out3_P, LTC6952_1_MATCH_Out4_N, LTC6952_1_MATCH_Out4_P, LTC6952_1_MATCH_Out5_N, LTC6952_1_MATCH_Out5_P, LTC6952_1_MATCH_Out6_N, LTC6952_1_MATCH_Out6_P, LTC6952_1_MATCH_Out7_N, LTC6952_1_MATCH_Out7_P, LTC6952_1_MATCH_Out8_N, LTC6952_1_MATCH_Out8_P, LTC6952_1_MATCH_Out9_N, LTC6952_1_MATCH_Out9_P, LTC6952_1_Out0_N, LTC6952_1_Out0_P, LTC6952_1_Out1_N, LTC6952_1_Out1_P, LTC6952_1_Out2_N, LTC6952_1_Out2_P, LTC6952_1_Out3_N, LTC6952_1_Out3_P, LTC6952_1_Out4_N, LTC6952_1_Out4_P, LTC6952_1_Out5_N, LTC6952_1_Out5_P, LTC6952_1_Out6_N, LTC6952_1_Out6_P, LTC6952_1_Out7_N, LTC6952_1_Out7_P, LTC6952_1_Out8_N, LTC6952_1_Out8_P, LTC6952_1_Out9_N, LTC6952_1_Out9_P, LTC6952_1_Out10_N, LTC6952_1_Out10_P, LTC6952_1_REF_MATCH_N, LTC6952_1_REF_MATCH_P
net class LTC_6952_2_REF_SMA: LTC6952_1_C_N, LTC6952_1_C_P
net class Single_50: LTC6952_1_C_N, LTC6952_1_C_Out10_N, LTC6952_1_C_Out10_P, LTC6952_1_C_P, LTC6952_1_MATCH_Out0_N, LTC6952_1_MATCH_Out0_P, LTC6952_1_MATCH_Out1_N, LTC6952_1_MATCH_Out1_P, LTC6952_1_MATCH_Out2_N, LTC6952_1_MATCH_Out2_P, LTC6952_1_MATCH_Out3_N, LTC6952_1_MATCH_Out3_P, LTC6952_1_MATCH_Out4_N, LTC6952_1_MATCH_Out4_P, LTC6952_1_MATCH_Out5_N, LTC6952_1_MATCH_Out5_P, LTC6952_1_MATCH_Out6_N, LTC6952_1_MATCH_Out6_P, LTC6952_1_MATCH_Out7_N, LTC6952_1_MATCH_Out7_P, LTC6952_1_MATCH_Out8_N, LTC6952_1_MATCH_Out8_P, LTC6952_1_MATCH_Out9_N, LTC6952_1_MATCH_Out9_P, LTC6952_1_Out0_N, LTC6952_1_Out0_P, LTC6952_1_Out1_N, LTC6952_1_Out1_P, LTC6952_1_Out2_N, LTC6952_1_Out2_P, LTC6952_1_Out3_N, LTC6952_1_Out3_P, LTC6952_1_Out4_N, LTC6952_1_Out4_P, LTC6952_1_Out5_N, LTC6952_1_Out5_P, LTC6952_1_Out6_N, LTC6952_1_Out6_P, LTC6952_1_Out7_N, LTC6952_1_Out7_P, LTC6952_1_Out8_N, LTC6952_1_Out8_P, LTC6952_1_Out9_N, LTC6952_1_Out9_P, LTC6952_1_Out10_N, LTC6952_1_Out10_P, LTC6952_1_REF_MATCH_N, LTC6952_1_REF_MATCH_P
net class CLK_SMA1_C: LTC6952_1_C_Out10_N, LTC6952_1_C_Out10_P
net class LTC_6952_2_MATCH_REF: LTC6952_1_REF_MATCH_N, LTC6952_1_REF_MATCH_P
net class SPI_LTC_0: SPI_6952_1_CLK, SPI_6952_1_CS, SPI_6952_1_MISO, SPI_6952_1_MOSI

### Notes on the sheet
- (near R1091) Zamieniona polaryzacja
- (near R1093) Zamieniona polaryzacja
- Zamieniona polaryzacja

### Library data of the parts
C41 C796-C802 C805-C808 C811-C814 C817 C818 = Capacitor: as C588 on sheet WR_Clock
C51 C52 = Capacitor: as C326 on sheet CLK_Mux
C118#1 C119#1 = Capacitor: Manufacturer: KEMET; Manufacturer Part Number: C0402C103K4RACTU; Dielectric Material: Ceramic; Tolerance: 10%; Voltage Rating (DC): 16V; Dielectric: X7R; Dissipation Factor: 3.5%
J4-J7 = 1909763-1: Ultra Miniature Coaxial Connector Jack, 60 V, 50 Ohm, -40 to 90 degC, RoHS, Tape and Reel; Brand: TE Connectivity / AMP; Maximum Frequency: 6 GHz; Gender: Jack (Female); Body Material: Liquid Crystal Polymer (LCP); RF Series: UMCC; Impedance: 50 Ohms
R270 R535 R536 = Resistor: as R311 on sheet WR_Clock
R534 = Resistor: Res Thick Film 0402 160 Ohm 1% 1/16W 100ppm/C Molded SMD SMD Paper T/R; Manufacturer: Stackpole Electronics; Manufacturer Part Number: RMCF0402FT160R; Temperature Coefficient: 100ppm/°C
R1077 R1080 R1091-R1094 R1097 R1098 R1100 R1101 R1103-R1106 R1109 R1110 = Resistor: as R1095 on sheet LED_US_1
U13 = LTC6952: Dystrybutor Zegarów; Manufacturer: Analog Devices; Manufacturer Part Number: LTC6952IUKG#PBF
